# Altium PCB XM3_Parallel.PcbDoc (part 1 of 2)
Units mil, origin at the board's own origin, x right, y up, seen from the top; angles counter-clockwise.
Board outline 8400 x 9001.8 mil, 4 copper layers (TOP, LAYER2, LAYER3, BOTTOM), stack 92 mil thick; 63 components, 9 nets, 170 pads, 4103 vias.
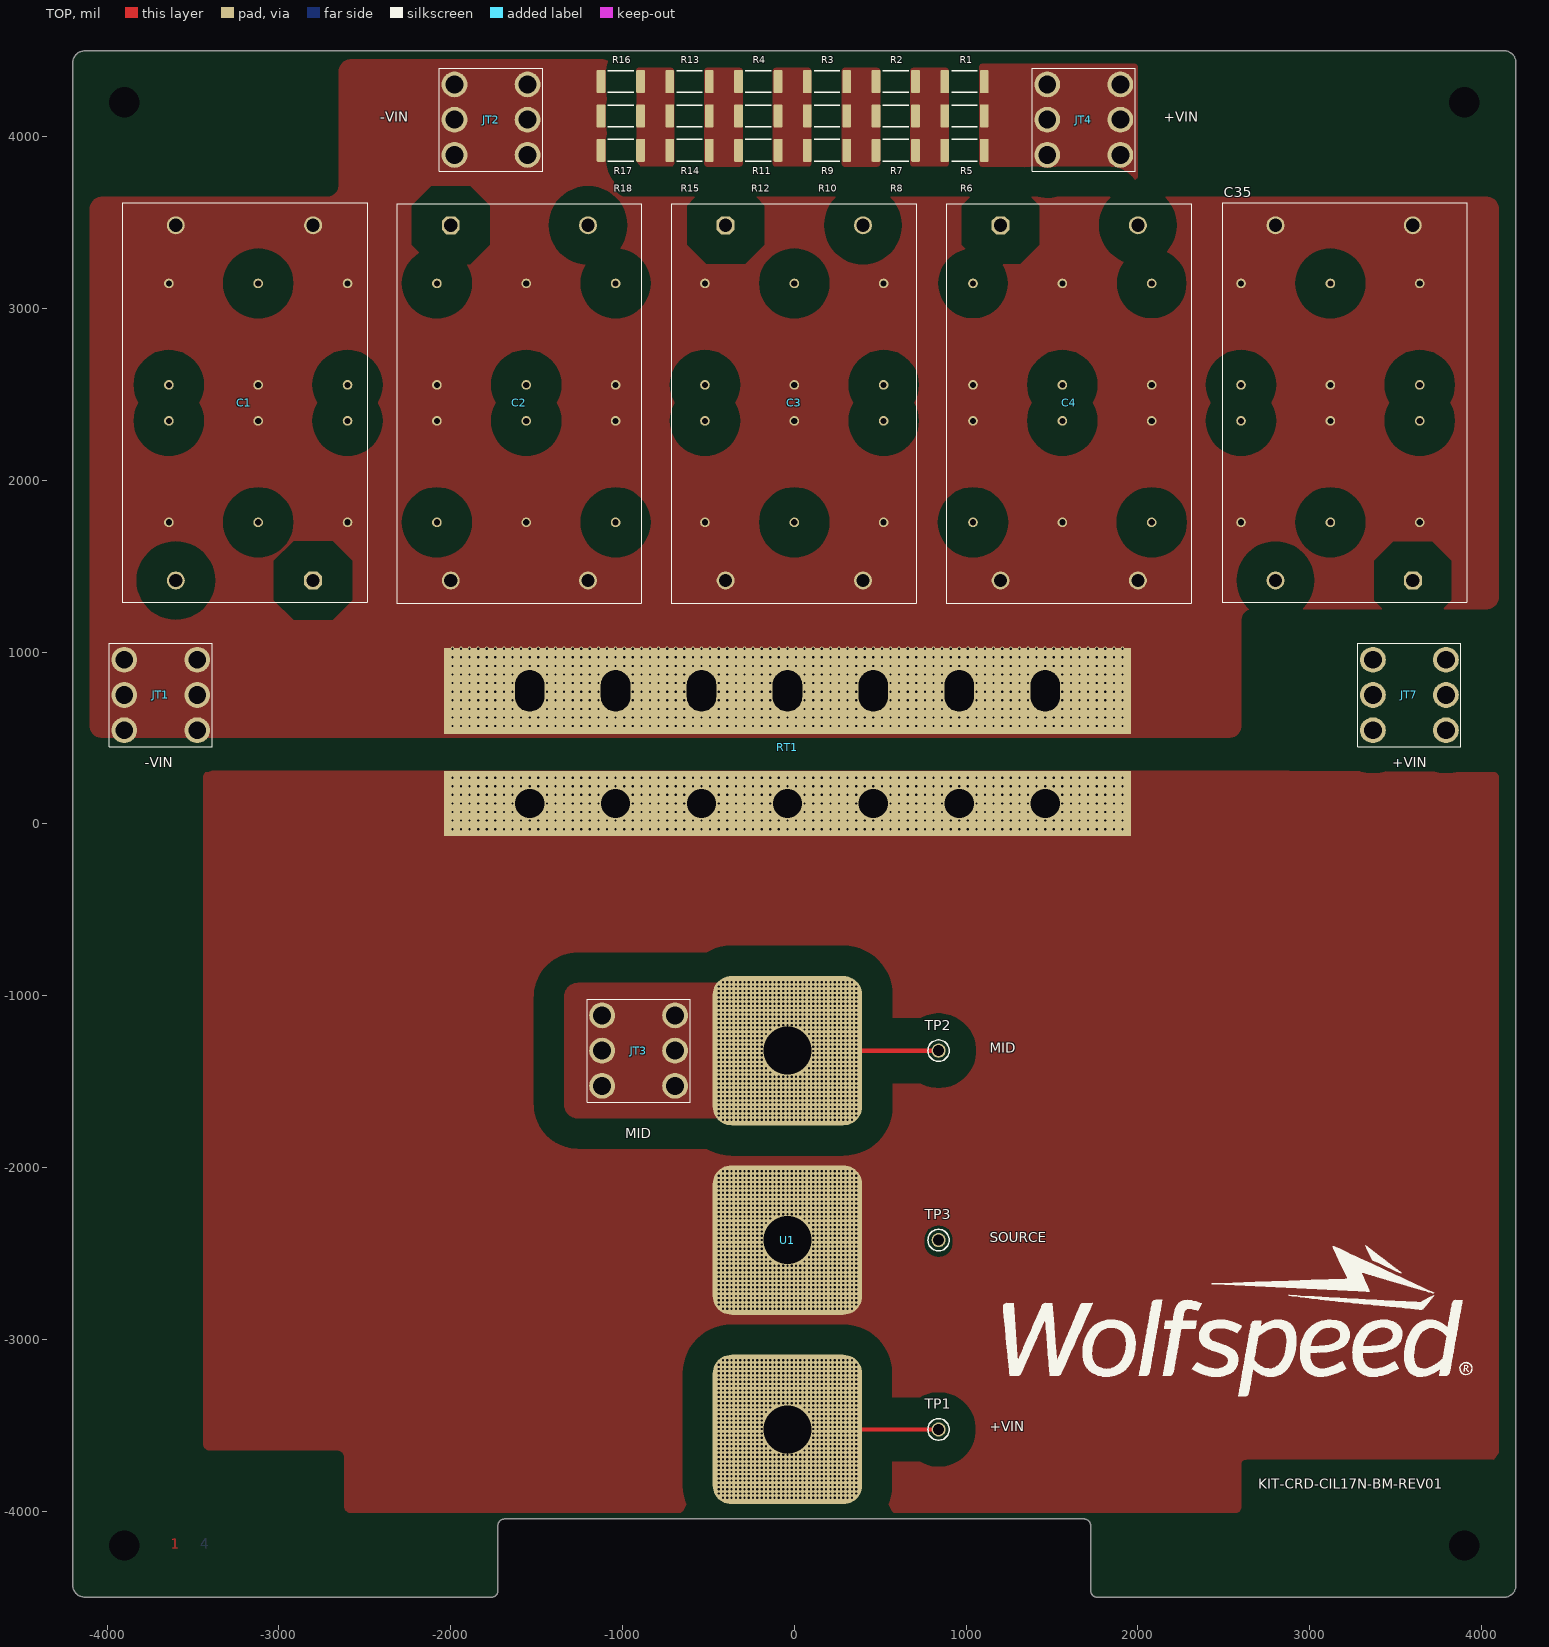
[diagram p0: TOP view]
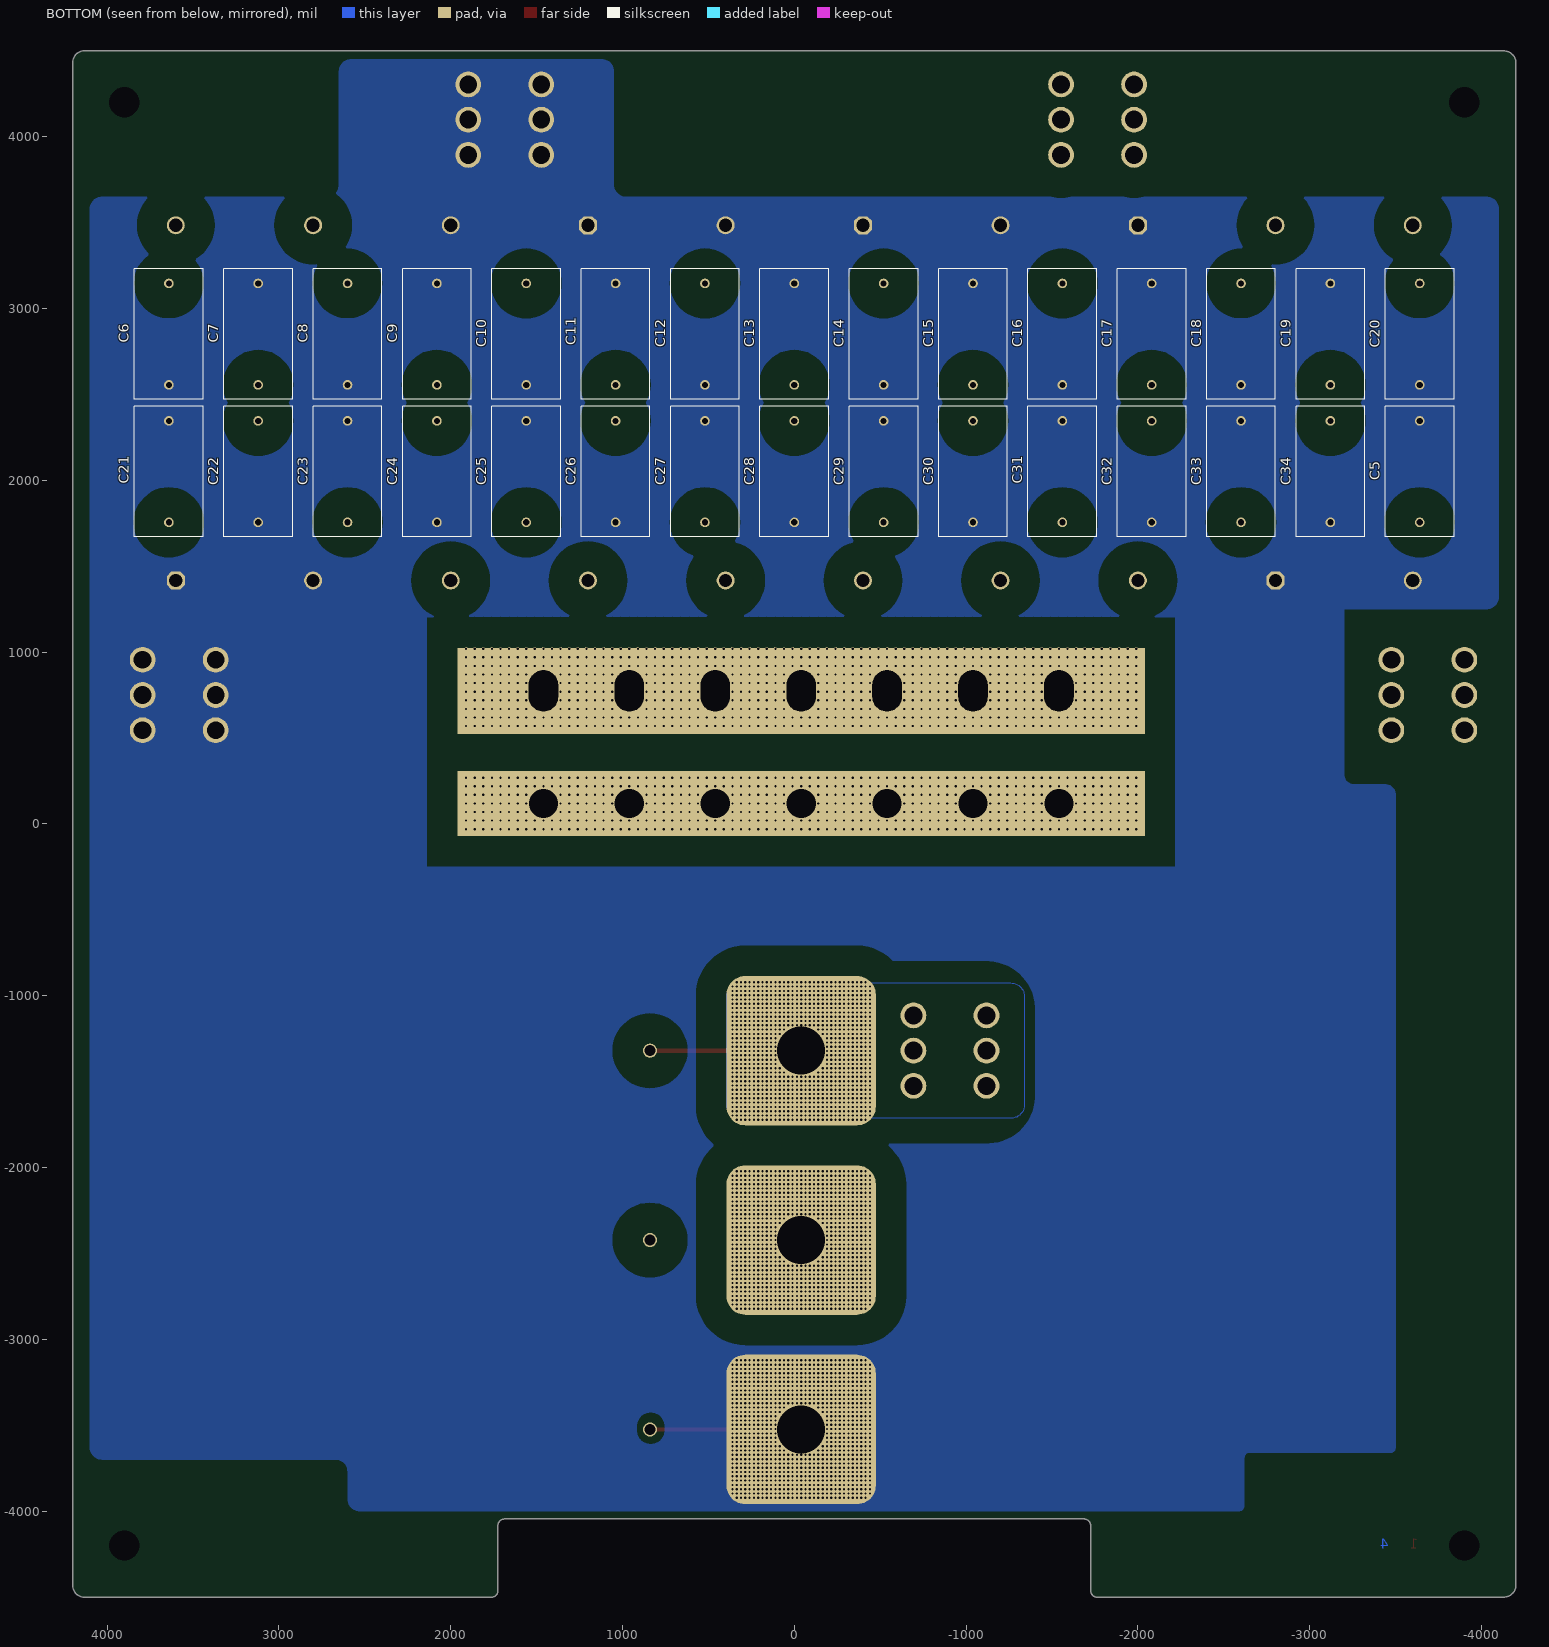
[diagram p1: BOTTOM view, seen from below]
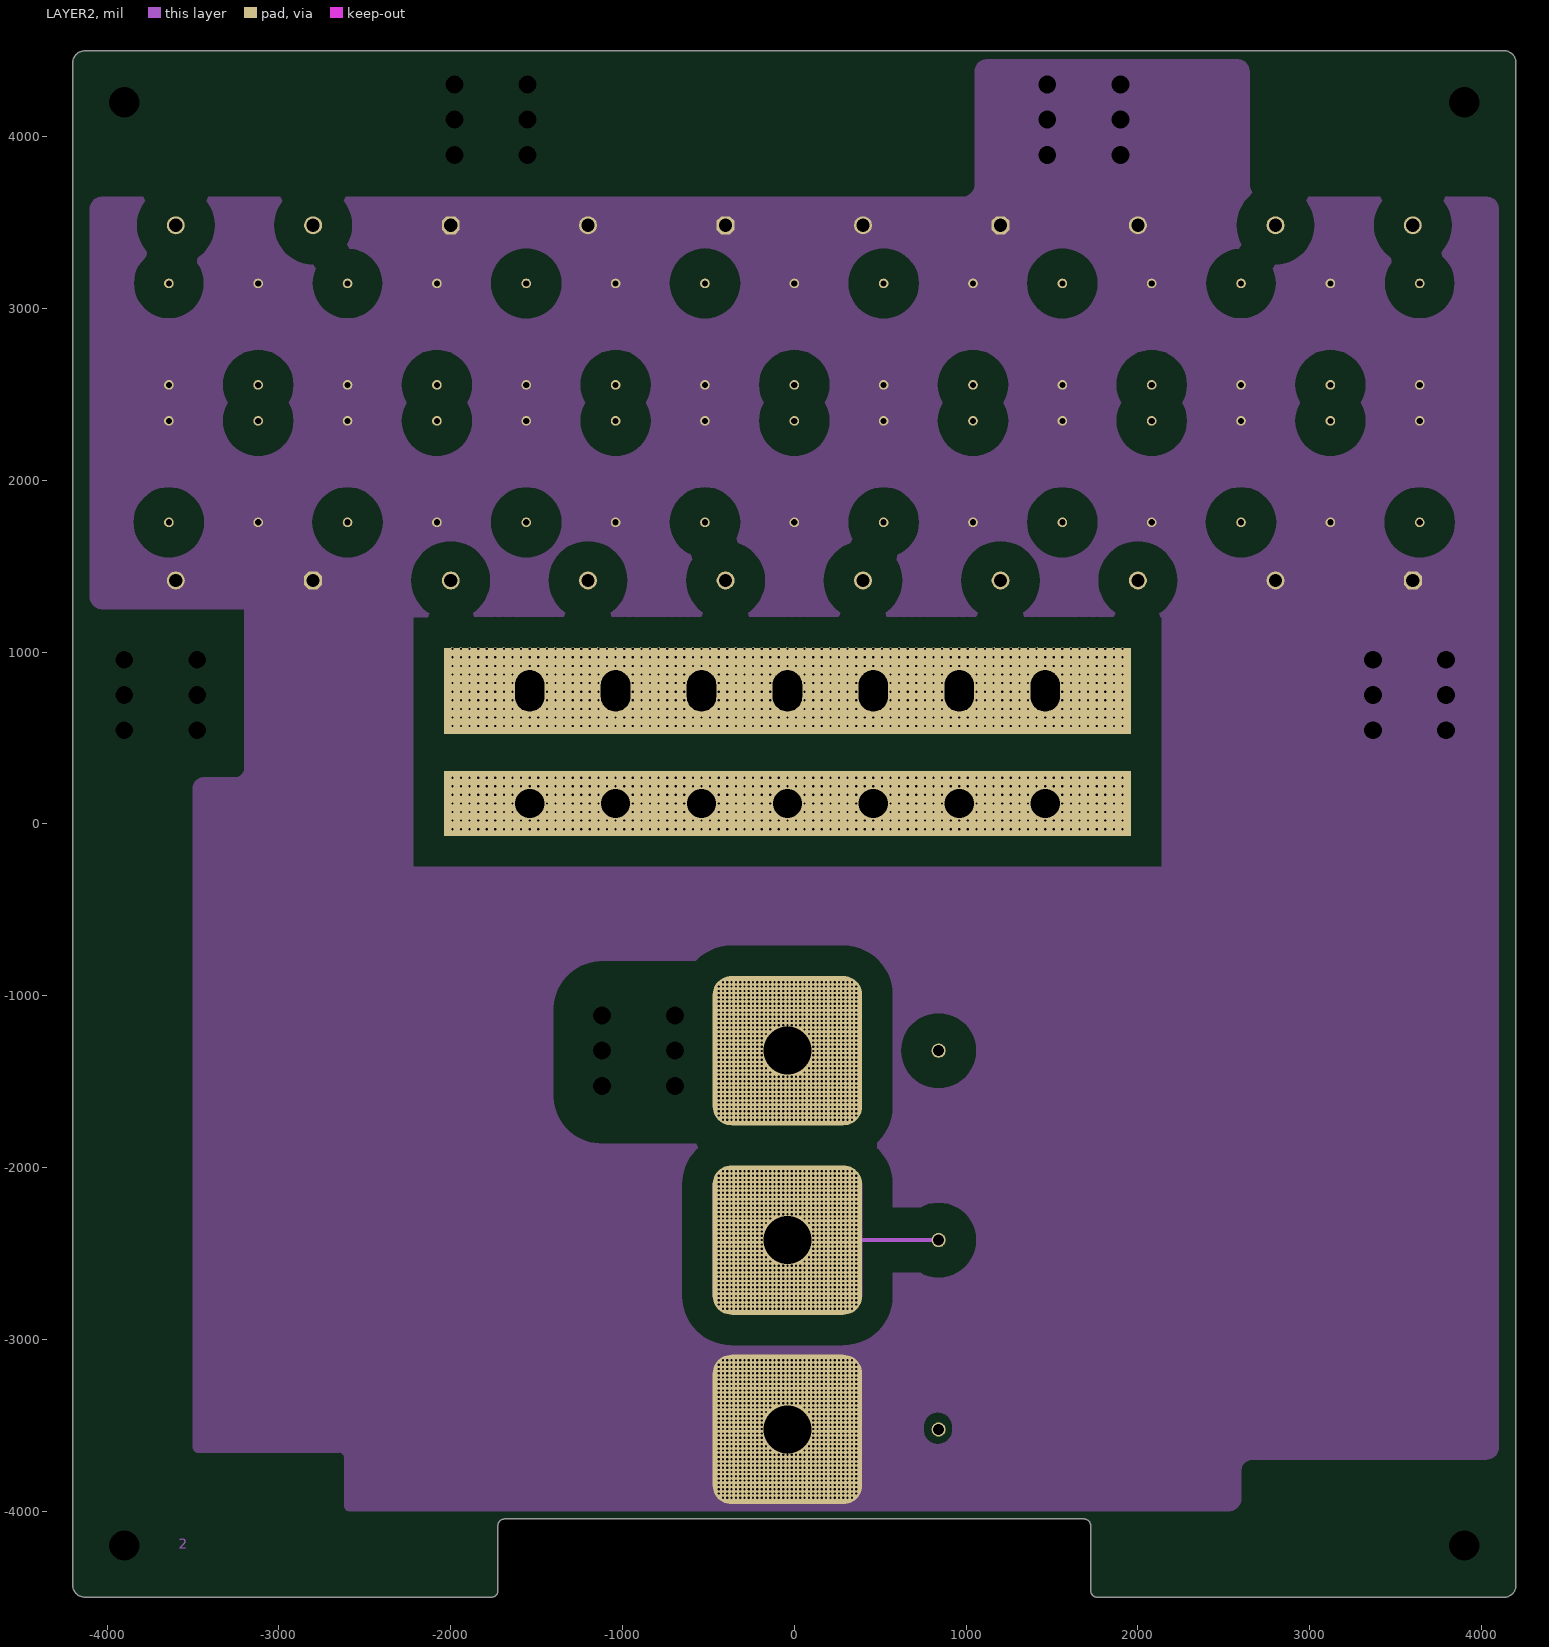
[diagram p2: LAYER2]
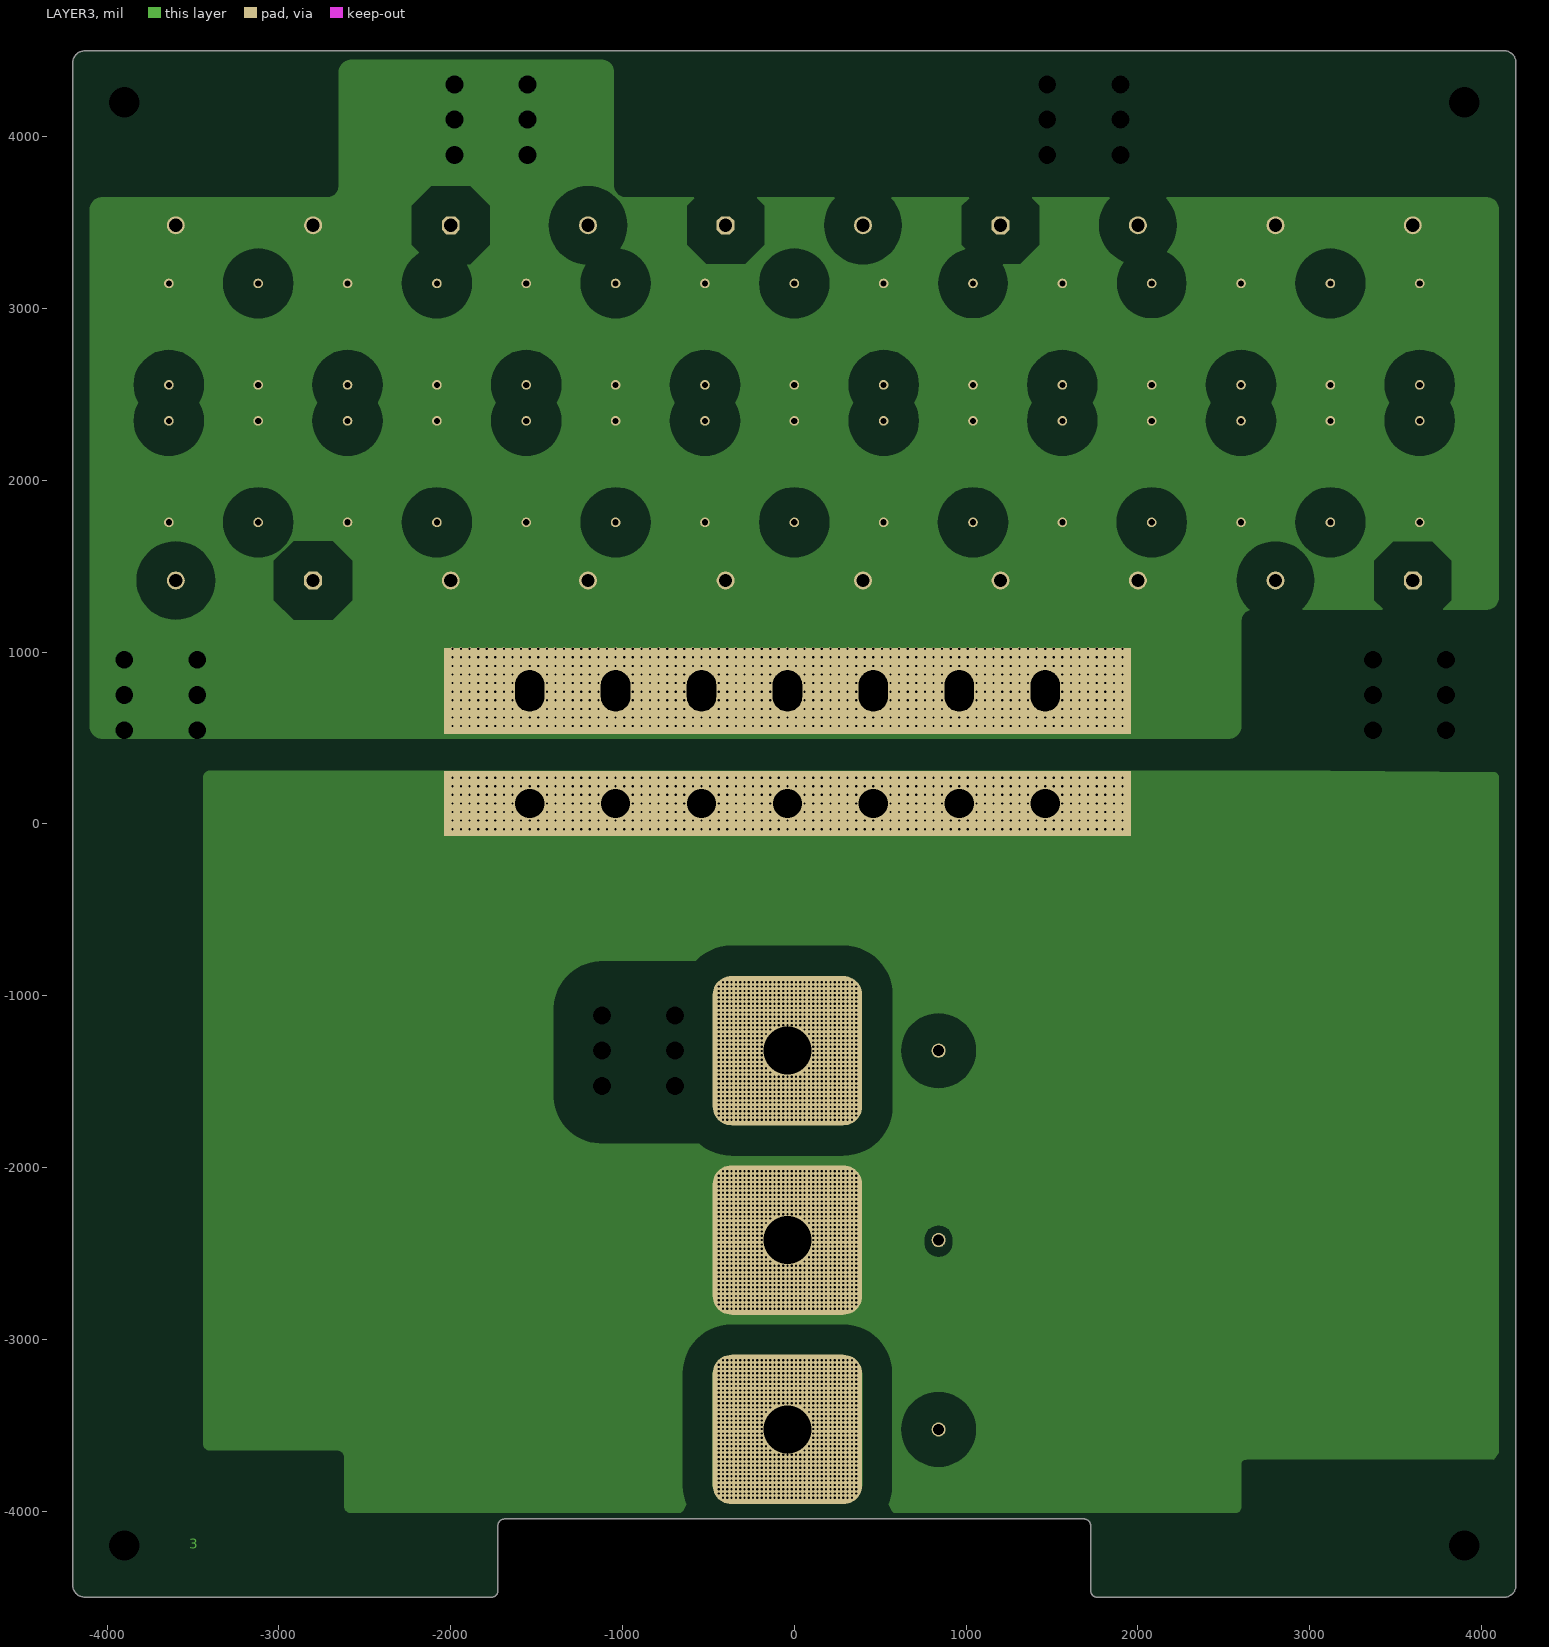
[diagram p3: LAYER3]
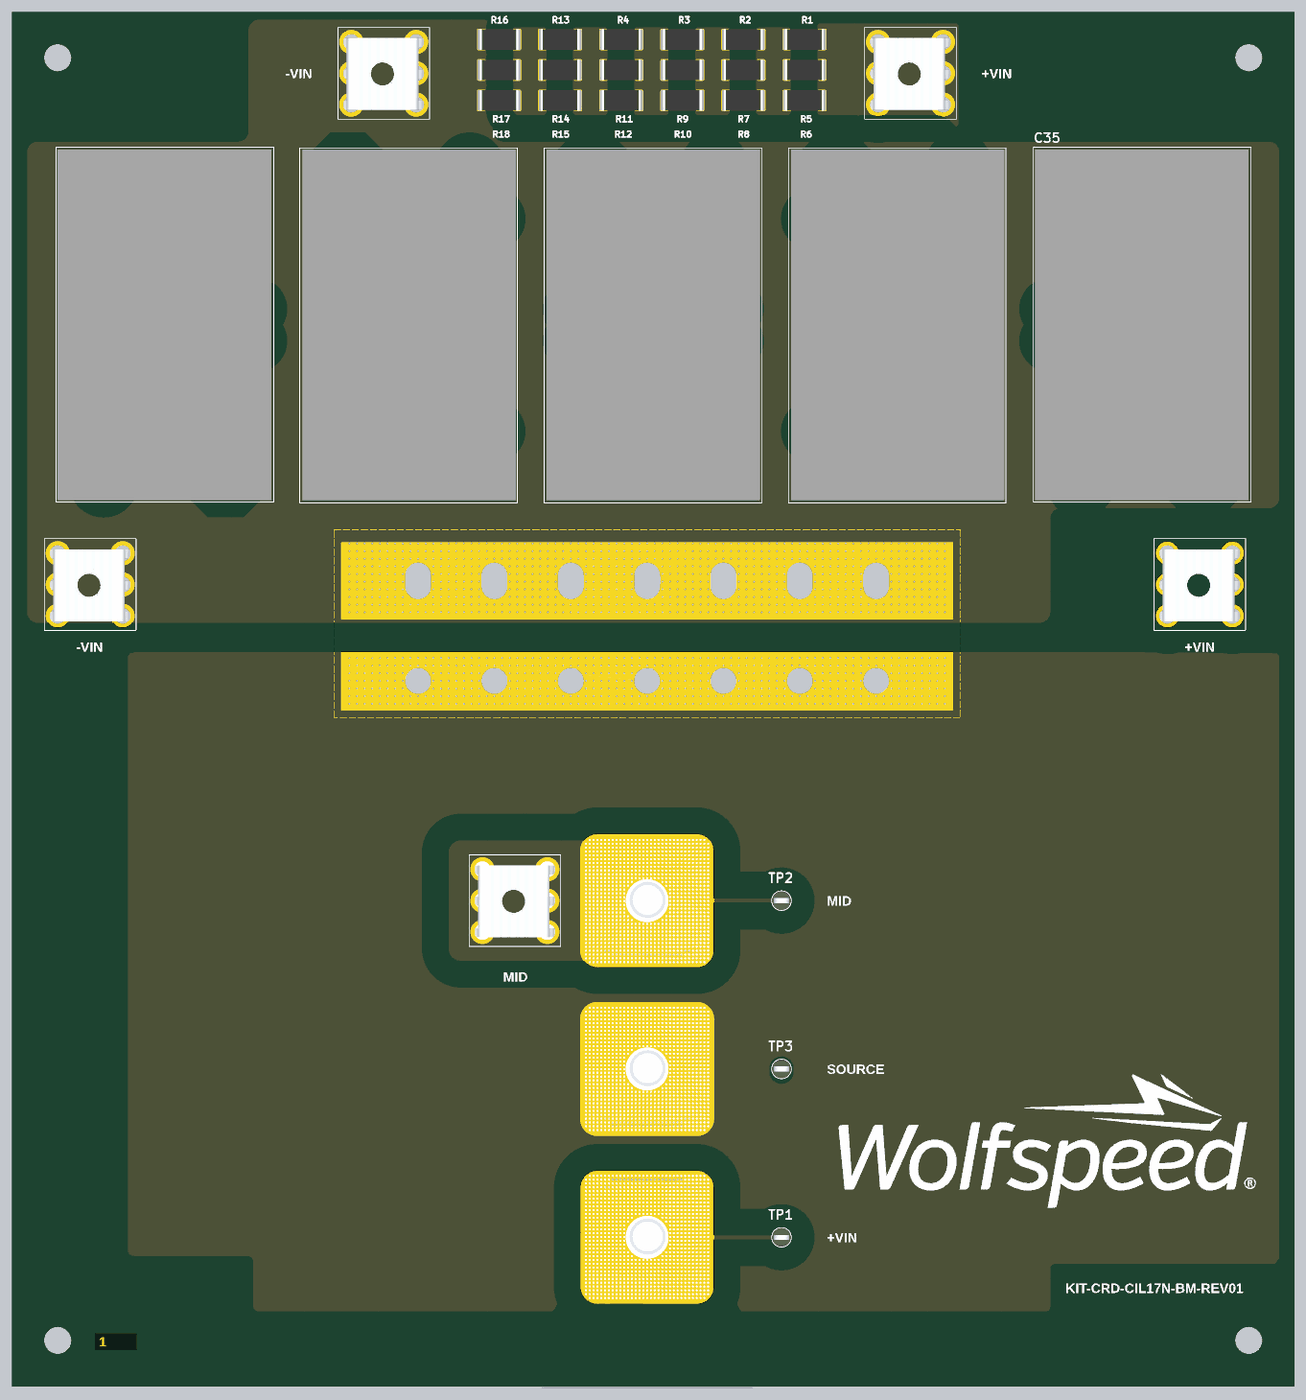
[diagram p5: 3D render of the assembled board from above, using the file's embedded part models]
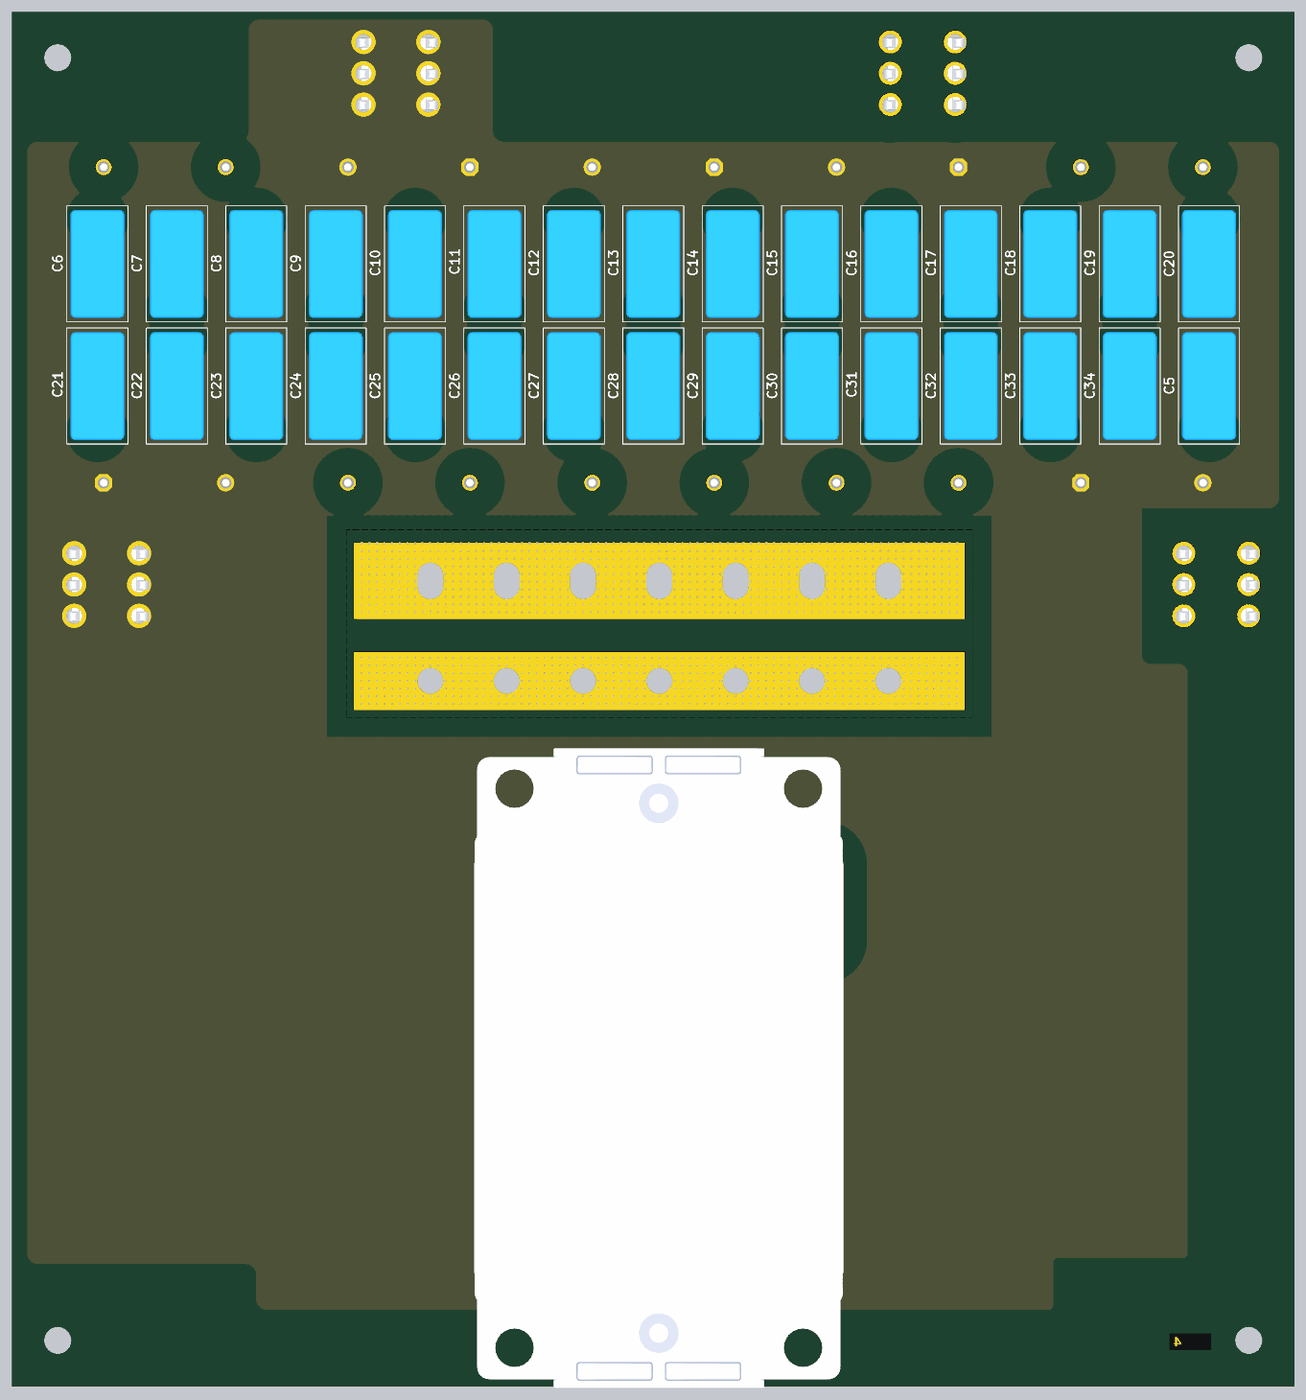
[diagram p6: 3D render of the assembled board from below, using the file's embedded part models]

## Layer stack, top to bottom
TOP: signal copper 2.68
Dielectric 1: core 8, FR-4, Dk 4.5
LAYER2: signal copper 2.68
Dielectric2: core 65.28, FR-4, Dk 4.5
LAYER3: signal copper 2.68
Dielectric3: core 8, FR-4, Dk 4.5
BOTTOM: signal copper 2.68

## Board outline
4130,-4501.8 ccw(c4130,-4431.8) 4200,-4431.8 4200,4430 ccw(c4130,4430) 4130,4500 2952.37,4498.2 -4130,4498.2 ccw(c-4130,4428.2) -4200,4428.2 -4200,-4430 ccw(c-4130,-4430) -4130,-4500 -3286.49,-4501.8 -1764.37,-4501.8 ccw(c-1764.37,-4462.43) -1725,-4462.43 -1725,-4084.79 cw(c-1685.63,-4084.79) -1685.63,-4045.42 1685.63,-4045.42 cw(c1685.63,-4084.79) 1725,-4084.79 1725,-4462.43 ccw(c1764.37,-4462.43) 1764.37,-4501.8

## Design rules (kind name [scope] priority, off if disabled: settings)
Clearance HiPot_Clearance_1 [InNetClass('High_Potential') vs InNetClass('High_Potential')] p1 off: gap=220.47 ignorepadtopadclearanceinfootprint=TRUE
Clearance "Schematic Clearance Constraint_3" [InNet('SOURCE')] p2: gap=175.59 ignorepadtopadclearanceinfootprint=TRUE
Clearance "Schematic Clearance Constraint_2" [InNet('Midpoint')] p3: gap=175.59 ignorepadtopadclearanceinfootprint=TRUE
Clearance "Schematic Clearance Constraint_1" [InNet('+Vin')] p4: gap=175.59 ignorepadtopadclearanceinfootprint=TRUE
Clearance "Schematic Clearance Constraint" [InNet('-Vin')] p5: gap=175.59 ignorepadtopadclearanceinfootprint=TRUE
Clearance [All] p6: gap=10 ignorepadtopadclearanceinfootprint=FALSE except(0: Arc-Hole Track-Hole SMDPad-Hole THPad-Hole Via-Hole Fill-Hole Poly-Hole Region-Hole Text-Hole)
Height [All] p1: minheight=0 maxheight=3000 prefheight=500
HoleSize [All] p1: absolutevalues=TRUE maxlimit=1000 minlimit=1 maxpercent=80.000 minpercent=20.000
PlaneClearance [All] p1: clearance=275.59
PlaneConnect [All] p1: planeconnectstyle=Direct reliefexpansion=20 reliefentries=4 reliefconductorwidth=10 reliefairgap=10
PolygonConnect [All] p1: connectstyle=Direct reliefconductorwidth=10 reliefentries=4 polygonreliefangle="90 Angle" airgapwidth=10
RoomDefinition KIT-CRD-CIL12N-BM_Main [InComponentClass('KIT-CRD-CIL12N-BM_Main')] p1: confinementstyle=ConfineIn formatcopy=TRUE lockcomponents=FALSE outline -4000,-4525 3930,-4525 3930,4415 -4000,4415
RoutingVias [All] p1: holewidth=28 width=50 viastyle="Through Hole" minholewidth=5 minwidth=8 maxholewidth=28 maxwidth=50
SolderMaskExpansion [All] p1: expansion=4 istentingtop=FALSE
Width [All] p1: maxlimit=500 minlimit=5 preferedwidth=25
26 further rules are at their usual default settings.

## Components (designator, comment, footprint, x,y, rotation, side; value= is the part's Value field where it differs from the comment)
C1 "C4AQSBW5220A3NJ" C4AQSBW5220A3NJ -3200,2450 r180 top value=22uF
C2 "C4AQSBW5220A3NJ" C4AQSBW5220A3NJ -1600,2450 r0 top value=22uF
C3 "C4AQSBW5220A3NJ" C4AQSBW5220A3NJ 0,2450 r0 top value=22uF
C4 "C4AQSBW5220A3NJ" C4AQSBW5220A3NJ 1600,2450 r0 top value=22uF
C5 "B32022B3473M000" B32022B3473M000 -3640,2050 r180 bottom
C6 "B32022B3473M000" B32022B3473M000 3640,2850 r0 bottom
C7 "B32022B3473M000" B32022B3473M000 3120,2850 r180 bottom
C8 "B32022B3473M000" B32022B3473M000 2600,2850 r0 bottom
C9 "B32022B3473M000" B32022B3473M000 2080,2850 r180 bottom
C10 "B32022B3473M000" B32022B3473M000 1560,2850 r0 bottom
C11 "B32022B3473M000" B32022B3473M000 1040,2850 r180 bottom
C12 "B32022B3473M000" B32022B3473M000 520,2850 r0 bottom
C13 "B32022B3473M000" B32022B3473M000 0,2850 r180 bottom
C14 "B32022B3473M000" B32022B3473M000 -520,2850 r0 bottom
C15 "B32022B3473M000" B32022B3473M000 -1040,2850 r180 bottom
C16 "B32022B3473M000" B32022B3473M000 -1560,2850 r0 bottom
C17 "B32022B3473M000" B32022B3473M000 -2080,2850 r180 bottom
C18 "B32022B3473M000" B32022B3473M000 -2600,2850 r0 bottom
C19 "B32022B3473M000" B32022B3473M000 -3120,2850 r180 bottom
C20 "B32022B3473M000" B32022B3473M000 -3640,2850 r0 bottom
C21 "B32022B3473M000" B32022B3473M000 3640,2050 r180 bottom
C22 "B32022B3473M000" B32022B3473M000 3120,2050 r0 bottom
C23 "B32022B3473M000" B32022B3473M000 2600,2050 r180 bottom
C24 "B32022B3473M000" B32022B3473M000 2080,2050 r0 bottom
C25 "B32022B3473M000" B32022B3473M000 1560,2050 r180 bottom
C26 "B32022B3473M000" B32022B3473M000 1040,2050 r0 bottom
C27 "B32022B3473M000" B32022B3473M000 520,2050 r180 bottom
C28 "B32022B3473M000" B32022B3473M000 0,2050 r0 bottom
C29 "B32022B3473M000" B32022B3473M000 -520,2050 r180 bottom
C30 "B32022B3473M000" B32022B3473M000 -1040,2050 r0 bottom
C31 "B32022B3473M000" B32022B3473M000 -1560,2050 r180 bottom
C32 "B32022B3473M000" B32022B3473M000 -2080,2050 r0 bottom
C33 "B32022B3473M000" B32022B3473M000 -2600,2050 r180 bottom
C34 "B32022B3473M000" B32022B3473M000 -3120,2050 r0 bottom
C35 "C4AQSBW5220A3NJ" C4AQSBW5220A3NJ 3200,2450 r180 top value=22uF
JT1 "8196" 8196 -3687.21,750 r270 top
JT2 "8196" 8196 -1765,4098.2 r270 top
JT3 "8196" 8196 -906.05,-1319.9 r270 top
JT4 "8196" 8196 1685,4098.2 r270 top
JT7 "8196" 8196 3580,750 r270 top
R1 "2176071-6" RESC6432X06N 990.43,4320 r180 top
R2 "2176071-6" RESC6432X06N 590.43,4320 r0 top
R3 "2176071-6" RESC6432X06N 190.43,4320 r180 top
R4 "2176071-6" RESC6432X06N -209.57,4320 r0 top
R5 "2176071-6" RESC6432X06N 990.43,4120 r180 top
R6 "2176071-6" RESC6432X06N 990.43,3920 r180 top
R7 "2176071-6" RESC6432X06N 590.43,4120 r0 top
R8 "2176071-6" RESC6432X06N 590.43,3920 r0 top
R9 "2176071-6" RESC6432X06N 190.43,4120 r180 top
R10 "2176071-6" RESC6432X06N 190.43,3920 r180 top
R11 "2176071-6" RESC6432X06N -209.57,4120 r0 top
R12 "2176071-6" RESC6432X06N -209.57,3920 r0 top
R13 "2176071-6" RESC6432X06N -609.57,4320 r180 top
R14 "2176071-6" RESC6432X06N -609.57,4120 r180 top
R15 "2176071-6" RESC6432X06N -609.57,3920 r180 top
R16 "2176071-6" RESC6432X06N -1009.57,4320 r0 top
R17 "2176071-6" RESC6432X06N -1009.57,4120 r0 top
R18 "2176071-6" RESC6432X06N -1009.57,3920 r0 top
RT1 "W-2-0025-4FC" tm_cvr_w_14pin_slots -40,493.94 r0 top
TP1 "5011" KSTN-5011_V 840,-3524.76 r0 top
TP2 "5011" KSTN-5011_V 840,-1320.04 r0 top
TP3 "5011" KSTN-5011_V 840,-2422.4 r0 top
U1 "BMx_Module" 62mm_BM_Module -39.95,-2422.4 r0 top

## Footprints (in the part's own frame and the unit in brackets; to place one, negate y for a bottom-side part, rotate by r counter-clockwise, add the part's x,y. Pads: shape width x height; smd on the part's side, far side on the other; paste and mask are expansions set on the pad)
62mm_BM_Module [mil]
  rrect25% 870x870 hole 280: 1(0,1102.36) 2(0,0) 3(0,-1102.36)
  body extent -1205,-2089 1212,2099, height 1168
8196 [mil]
  round 150 / inner round 60 / far side round 150 hole 103.94: 1(-205,-212.5) 2(0,-212.5) 3(205,-212.5) 4(205,212.5) 5(0,212.5) 6(-205,212.5)
  silkscreen extent -300,-300 300,300, body extent -230,-278 240,262, height 454
B32022B3473M000 [mil]
  round 56 hole 36 mask+0: 1(0,-295.28) 2(0,295.28)
  silkscreen extent -200,-380 200,380, body extent -177,-354 177,354, height 689
C4AQSBW5220A3NJ [mm] "C4AQSBW5220A3NJ Unchecked Film; Metallized Polypropylene; DC Link; C4AQ; Automotive Grade; 22 uF; 5%; 1; 50 Film Capacitors 8.13"
  oct 2.65x2.65 hole 1.95: 1(-10.15,26.25)
  round 2.65 hole 1.95: 2(10.15,26.25) 3(-10.15,-26.25) 4(10.15,-26.25)
  silkscreen extent -18.16,-29.59 18.03,29.46, body extent -17.73,-29.15 17.78,29.15, height 50.31
KSTN-5011_V [mm] "Test Point, Dia 3.17mm"
  round 2.1 hole 1.6: 1(0,0)
  silkscreen extent -1.59,-1.58 1.59,1.58, body extent -1.59,-1.59 1.59,1.59, height 8.13
RESC6432X06N [mm] "Chip Resistor, 2-Leads, Body 6.35x3.20mm, IPC Medium Density"
  rrect25% 1.3x3.4 smd: 1(-2.925,0) 2(2.925,0)
  silkscreen extent -1.9,-1.6 1.9,1.6, body extent -3.22,-1.7 3.22,1.7, height 0.65
tm_cvr_w_14pin_slots [mil]
  round 300 / inner round 60 / far side round 300 hole 170: 1(-1500,-375) 2(-1000,-375) 3(-500,-375) 5(500,-375) 6(1000,-375) 7(1500,-375)
  rect 4000x380 hole 170: 4(0,-375)
  oval 300x370 / inner round 60 / far side oval 300x370 hole 170 slot 240 at 90 deg: 8(1500,280) 9(1000,280) 10(500,280) 12(-500,280) 13(-1000,280) 14(-1500,280)
  rect 4000x500 hole 170 slot 240 at 90 deg: 11(0,280)

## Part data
C1 C2 C3 C4 C35: "C4AQSBW5220A3NJ Unchecked Film; Metallized Polypropylene; DC Link; C4AQ; Automotive Grade; 22 uF; 5%; 1; 50 Film Capacitors 8.13", Manufacturer=Kemet, Tolerence=5%, Voltage Rating=1500VDC
C5 C6 C7 C8 C9 C10 C11 C12 C13 C14 C15 C16 C17 C18 C19 C20 C21 C22 C23 C24 C25 C26 C27 C28 C29 C30 C31 C32 C33 C34: "Cap Film 0.047uF 300VAC PP 20% 18 X 9 X 17.5mm RDL 15mm Bulk", Capacitance=47nF, Dielectric=PP, Dielectric Material=Polypropylene, Insulation Resistance=100R, Manufacturer="TDK EPCOS", Max Operating Temperature=110°C, Min Operating Temperature=-40°C, Supplier Part Number 1=495-4769-ND, Tolerance=20%, Voltage=1.5kV
JT1 JT2 JT3 JT4 JT7: library part "Conn Plug 6", "TERMINAL SCREW PC HEAVY DUTY", Manufacturer="Keystone Electronics"
R1 R2 R3 R4 R5 R6 R7 R8 R9 R10 R11 R12 R13 R14 R15 R16 R17 R18: "Res Thick Film 2512 220K Ohm 1% 2W ±100ppm/°C Molded SMD T/R", Case Code (Imperial)=2512, Case Code (Metric)=6432, Manufacturer="TE Connectivity", Max Operating Temperature=155°C, Max Power Dissipation=2W, Min Operating Temperature=-55°C, Package Quantity=4000, Resistance=220kR, Resistor Type="Thick Film", Supplier Part Number 1=01AH0733, Temperature Coefficient=100ppm/°C, Tolerance=1%
TP1 TP2 TP3: "Test Point, Black, Through Hole, RoHS, Bulk", Colour=Black, Manufacturer=Keystone, Package Quantity=100

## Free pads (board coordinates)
  round 104.33 hole 177.17 unplated: 0(-3900,-4200) 1(3900,-4200) 2(3900,4200) 3(-3900,4200)

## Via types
v1: diameter 24/20/20/20 (per signal layer), hole 13, TOP to BOTTOM, tented both sides, 4103 vias

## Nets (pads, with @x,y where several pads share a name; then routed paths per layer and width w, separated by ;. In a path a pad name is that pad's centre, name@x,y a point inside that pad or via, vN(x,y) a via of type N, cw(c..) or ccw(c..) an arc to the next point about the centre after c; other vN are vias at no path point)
+VIN: C1.1 C1.2 C2.1 C2.2 C3.1 C3.2 C4.1 C4.2 C5.2 C6.2 C7.2 C8.2 C9.2 C10.2 C11.2 C12.2 C13.2 C14.2 C15.2 C16.2 C17.2 C18.2 C19.2 C20.2 C21.2 C22.2 C23.2 C24.2 C25.2 C26.2 C27.2 C28.2 C29.2 C30.2 C31.2 C32.2 C33.2 C34.2 C35.1 C35.2 JT4.1 JT4.2 JT4.3 JT4.4 JT4.5 JT4.6 JT7.1 JT7.2 JT7.3 JT7.4 JT7.5 JT7.6 R1.1 R5.1 R6.1 TP1.1 U1.3 | length 880
  TOP w25: U1.3@-39.95,-3524.76 310.05,-3524.76 TP1.1@840,-3524.76
  other v1: -414.95,-3922.4 -389.95,-3922.4 -364.95,-3922.4 -339.95,-3922.4 -314.95,-3922.4 -289.95,-3922.4 -264.95,-3922.4 -239.95,-3922.4 -214.95,-3922.4 -189.95,-3922.4 -164.95,-3922.4 -139.95,-3922.4 -114.95,-3922.4 -89.95,-3922.4 -64.95,-3922.4 -39.95,-3922.4 -14.95,-3922.4 10.05,-3922.4 35.05,-3922.4 60.05,-3922.4 85.05,-3922.4 110.05,-3922.4 135.05,-3922.4 160.05,-3922.4 185.05,-3922.4 210.05,-3922.4 235.05,-3922.4 260.05,-3922.4 285.05,-3922.4 310.05,-3922.4 335.05,-3922.4 -439.95,-3897.4 -414.95,-3897.4 -389.95,-3897.4 -364.95,-3897.4 -339.95,-3897.4 -314.95,-3897.4 -289.95,-3897.4 -264.95,-3897.4 -239.95,-3897.4 -214.95,-3897.4 -189.95,-3897.4 -164.95,-3897.4 -139.95,-3897.4 -114.95,-3897.4 -89.95,-3897.4 -64.95,-3897.4 -39.95,-3897.4 -14.95,-3897.4 10.05,-3897.4 35.05,-3897.4 60.05,-3897.4 85.05,-3897.4 110.05,-3897.4 135.05,-3897.4 160.05,-3897.4 185.05,-3897.4 210.05,-3897.4 235.05,-3897.4 260.05,-3897.4 285.05,-3897.4 310.05,-3897.4 335.05,-3897.4 360.05,-3897.4 -439.95,-3872.4 -414.95,-3872.4 -389.95,-3872.4 -364.95,-3872.4 -339.95,-3872.4 -314.95,-3872.4 -289.95,-3872.4 -264.95,-3872.4 -239.95,-3872.4 -214.95,-3872.4 -189.95,-3872.4 -164.95,-3872.4 -139.95,-3872.4 -114.95,-3872.4 -89.95,-3872.4 -64.95,-3872.4 -39.95,-3872.4 -14.95,-3872.4 10.05,-3872.4 35.05,-3872.4 60.05,-3872.4 85.05,-3872.4 110.05,-3872.4 135.05,-3872.4 160.05,-3872.4 185.05,-3872.4 210.05,-3872.4 235.05,-3872.4 260.05,-3872.4 285.05,-3872.4 310.05,-3872.4 335.05,-3872.4 360.05,-3872.4 -439.95,-3847.4 -414.95,-3847.4 -389.95,-3847.4 -364.95,-3847.4 -339.95,-3847.4 -314.95,-3847.4 -289.95,-3847.4 -264.95,-3847.4 -239.95,-3847.4 -214.95,-3847.4 -189.95,-3847.4 -164.95,-3847.4 -139.95,-3847.4 -114.95,-3847.4 -89.95,-3847.4 -64.95,-3847.4 -39.95,-3847.4 -14.95,-3847.4 10.05,-3847.4 35.05,-3847.4 60.05,-3847.4 85.05,-3847.4 110.05,-3847.4 135.05,-3847.4 160.05,-3847.4 185.05,-3847.4 210.05,-3847.4 235.05,-3847.4 260.05,-3847.4 285.05,-3847.4 310.05,-3847.4 335.05,-3847.4 360.05,-3847.4 -439.95,-3822.4 -414.95,-3822.4 -389.95,-3822.4 -364.95,-3822.4 -339.95,-3822.4 -314.95,-3822.4 -289.95,-3822.4 -264.95,-3822.4 -239.95,-3822.4 -214.95,-3822.4 -189.95,-3822.4 -164.95,-3822.4 -139.95,-3822.4 -114.95,-3822.4 -89.95,-3822.4 -64.95,-3822.4 -39.95,-3822.4 -14.95,-3822.4 10.05,-3822.4 35.05,-3822.4 60.05,-3822.4 85.05,-3822.4 110.05,-3822.4 135.05,-3822.4 160.05,-3822.4 185.05,-3822.4 210.05,-3822.4 235.05,-3822.4 260.05,-3822.4 285.05,-3822.4 310.05,-3822.4 335.05,-3822.4 360.05,-3822.4 -439.95,-3797.4 -414.95,-3797.4 -389.95,-3797.4 -364.95,-3797.4 -339.95,-3797.4 -314.95,-3797.4 -289.95,-3797.4 -264.95,-3797.4 -239.95,-3797.4 -214.95,-3797.4 -189.95,-3797.4 -164.95,-3797.4 -139.95,-3797.4 -114.95,-3797.4 -89.95,-3797.4 -64.95,-3797.4 -39.95,-3797.4 -14.95,-3797.4 10.05,-3797.4 35.05,-3797.4 60.05,-3797.4 85.05,-3797.4 110.05,-3797.4 135.05,-3797.4 160.05,-3797.4 185.05,-3797.4 210.05,-3797.4 235.05,-3797.4 260.05,-3797.4 285.05,-3797.4 310.05,-3797.4 335.05,-3797.4 360.05,-3797.4 -439.95,-3772.4 -414.95,-3772.4 -389.95,-3772.4 -364.95,-3772.4 -339.95,-3772.4 -314.95,-3772.4 -289.95,-3772.4 -264.95,-3772.4 -239.95,-3772.4 -214.95,-3772.4 -189.95,-3772.4 -164.95,-3772.4 -139.95,-3772.4 -114.95,-3772.4 -89.95,-3772.4 -64.95,-3772.4 -39.95,-3772.4 -14.95,-3772.4 10.05,-3772.4 35.05,-3772.4 60.05,-3772.4 85.05,-3772.4 110.05,-3772.4 135.05,-3772.4 160.05,-3772.4 185.05,-3772.4 210.05,-3772.4 235.05,-3772.4 260.05,-3772.4 285.05,-3772.4 310.05,-3772.4 335.05,-3772.4 360.05,-3772.4 -439.95,-3747.4 -414.95,-3747.4 -389.95,-3747.4 -364.95,-3747.4 -339.95,-3747.4 -314.95,-3747.4 -289.95,-3747.4 -264.95,-3747.4 -239.95,-3747.4 -214.95,-3747.4 -189.95,-3747.4 -164.95,-3747.4 -139.95,-3747.4 -114.95,-3747.4 -89.95,-3747.4 -64.95,-3747.4 -39.95,-3747.4 -14.95,-3747.4 10.05,-3747.4 35.05,-3747.4 60.05,-3747.4 85.05,-3747.4 110.05,-3747.4 135.05,-3747.4 160.05,-3747.4 185.05,-3747.4 210.05,-3747.4 235.05,-3747.4 260.05,-3747.4 285.05,-3747.4 310.05,-3747.4 335.05,-3747.4 360.05,-3747.4 -439.95,-3722.4 -414.95,-3722.4 -389.95,-3722.4 -364.95,-3722.4 -339.95,-3722.4 -314.95,-3722.4 -289.95,-3722.4 -264.95,-3722.4 -239.95,-3722.4 -214.95,-3722.4 -189.95,-3722.4 -164.95,-3722.4 -139.95,-3722.4 -114.95,-3722.4 -89.95,-3722.4 -64.95,-3722.4 -39.95,-3722.4 -14.95,-3722.4 10.05,-3722.4 35.05,-3722.4 60.05,-3722.4 85.05,-3722.4 110.05,-3722.4 135.05,-3722.4 160.05,-3722.4 185.05,-3722.4 210.05,-3722.4 235.05,-3722.4 260.05,-3722.4 285.05,-3722.4 310.05,-3722.4 335.05,-3722.4 360.05,-3722.4 -439.95,-3697.4 -414.95,-3697.4 -389.95,-3697.4 -364.95,-3697.4 -339.95,-3697.4 -314.95,-3697.4 -289.95,-3697.4 -264.95,-3697.4 -239.95,-3697.4 -214.95,-3697.4 -189.95,-3697.4 -164.95,-3697.4 -139.95,-3697.4 -114.95,-3697.4 -89.95,-3697.4 -64.95,-3697.4 -39.95,-3697.4 -14.95,-3697.4 10.05,-3697.4 35.05,-3697.4 60.05,-3697.4 85.05,-3697.4 110.05,-3697.4 135.05,-3697.4 160.05,-3697.4 185.05,-3697.4 210.05,-3697.4 235.05,-3697.4 260.05,-3697.4 285.05,-3697.4 310.05,-3697.4 335.05,-3697.4 360.05,-3697.4 -439.95,-3672.4 -414.95,-3672.4 -389.95,-3672.4 -364.95,-3672.4 -339.95,-3672.4 -314.95,-3672.4 -289.95,-3672.4 -264.95,-3672.4 -239.95,-3672.4 -214.95,-3672.4 -189.95,-3672.4 -164.95,-3672.4 -139.95,-3672.4 -114.95,-3672.4 -89.95,-3672.4 -64.95,-3672.4 -39.95,-3672.4 -14.95,-3672.4 10.05,-3672.4 35.05,-3672.4 60.05,-3672.4 85.05,-3672.4 110.05,-3672.4 135.05,-3672.4 160.05,-3672.4 185.05,-3672.4 210.05,-3672.4 235.05,-3672.4 260.05,-3672.4 285.05,-3672.4 310.05,-3672.4 335.05,-3672.4 360.05,-3672.4 -439.95,-3647.4 -414.95,-3647.4 -389.95,-3647.4 -364.95,-3647.4 -339.95,-3647.4 -314.95,-3647.4 -289.95,-3647.4 -264.95,-3647.4 -239.95,-3647.4 -214.95,-3647.4 -189.95,-3647.4 -164.95,-3647.4 -139.95,-3647.4 60.05,-3647.4 85.05,-3647.4 110.05,-3647.4 135.05,-3647.4 160.05,-3647.4 185.05,-3647.4 210.05,-3647.4 235.05,-3647.4 260.05,-3647.4 285.05,-3647.4 310.05,-3647.4 335.05,-3647.4 360.05,-3647.4 -439.95,-3622.4 -414.95,-3622.4 -389.95,-3622.4 -364.95,-3622.4 -339.95,-3622.4 -314.95,-3622.4 -289.95,-3622.4 -264.95,-3622.4 -239.95,-3622.4 -214.95,-3622.4 -189.95,-3622.4 -164.95,-3622.4 85.05,-3622.4 110.05,-3622.4 135.05,-3622.4 160.05,-3622.4 185.05,-3622.4 210.05,-3622.4 235.05,-3622.4 260.05,-3622.4 285.05,-3622.4 310.05,-3622.4 335.05,-3622.4 360.05,-3622.4 -439.95,-3597.4 -414.95,-3597.4 -389.95,-3597.4 -364.95,-3597.4 -339.95,-3597.4 -314.95,-3597.4 -289.95,-3597.4 -264.95,-3597.4 -239.95,-3597.4 -214.95,-3597.4 -189.95,-3597.4 110.05,-3597.4 135.05,-3597.4 160.05,-3597.4 185.05,-3597.4 210.05,-3597.4 235.05,-3597.4 260.05,-3597.4 285.05,-3597.4 310.05,-3597.4 335.05,-3597.4 360.05,-3597.4 -439.95,-3572.4 -414.95,-3572.4 -389.95,-3572.4 -364.95,-3572.4 -339.95,-3572.4 -314.95,-3572.4 -289.95,-3572.4 -264.95,-3572.4 -239.95,-3572.4 -214.95,-3572.4 -189.95,-3572.4 110.05,-3572.4 135.05,-3572.4 160.05,-3572.4 185.05,-3572.4 210.05,-3572.4 235.05,-3572.4 260.05,-3572.4 285.05,-3572.4 310.05,-3572.4 335.05,-3572.4 360.05,-3572.4 -439.95,-3547.4 -414.95,-3547.4 -389.95,-3547.4 -364.95,-3547.4 -339.95,-3547.4 -314.95,-3547.4 -289.95,-3547.4 -264.95,-3547.4 -239.95,-3547.4 -214.95,-3547.4 -189.95,-3547.4 110.05,-3547.4 135.05,-3547.4 160.05,-3547.4 185.05,-3547.4 210.05,-3547.4 235.05,-3547.4 260.05,-3547.4 285.05,-3547.4 310.05,-3547.4 335.05,-3547.4 360.05,-3547.4 -439.95,-3522.4 -414.95,-3522.4 -389.95,-3522.4 -364.95,-3522.4 -339.95,-3522.4 -314.95,-3522.4 -289.95,-3522.4 -264.95,-3522.4 -239.95,-3522.4 -214.95,-3522.4 -189.95,-3522.4 110.05,-3522.4 135.05,-3522.4 160.05,-3522.4 185.05,-3522.4 210.05,-3522.4 235.05,-3522.4 260.05,-3522.4 285.05,-3522.4 310.05,-3522.4 335.05,-3522.4 360.05,-3522.4 -439.95,-3497.4 -414.95,-3497.4 -389.95,-3497.4 -364.95,-3497.4 -339.95,-3497.4 -314.95,-3497.4 -289.95,-3497.4 -264.95,-3497.4 -239.95,-3497.4 -214.95,-3497.4 -189.95,-3497.4 110.05,-3497.4 135.05,-3497.4 160.05,-3497.4 185.05,-3497.4 210.05,-3497.4 235.05,-3497.4 260.05,-3497.4 285.05,-3497.4 310.05,-3497.4 335.05,-3497.4 360.05,-3497.4 -439.95,-3472.4 -414.95,-3472.4 -389.95,-3472.4 -364.95,-3472.4 -339.95,-3472.4 -314.95,-3472.4 -289.95,-3472.4 -264.95,-3472.4 -239.95,-3472.4 -214.95,-3472.4 -189.95,-3472.4 110.05,-3472.4 135.05,-3472.4 160.05,-3472.4 185.05,-3472.4 210.05,-3472.4 235.05,-3472.4 260.05,-3472.4 285.05,-3472.4 310.05,-3472.4 335.05,-3472.4 360.05,-3472.4 -439.95,-3447.4 -414.95,-3447.4 -389.95,-3447.4 -364.95,-3447.4 -339.95,-3447.4 -314.95,-3447.4 -289.95,-3447.4 -264.95,-3447.4 -239.95,-3447.4 -214.95,-3447.4 -189.95,-3447.4 110.05,-3447.4 135.05,-3447.4 160.05,-3447.4 185.05,-3447.4 210.05,-3447.4 235.05,-3447.4 260.05,-3447.4 285.05,-3447.4 310.05,-3447.4 335.05,-3447.4 360.05,-3447.4 -439.95,-3422.4 -414.95,-3422.4 -389.95,-3422.4 -364.95,-3422.4 -339.95,-3422.4 -314.95,-3422.4 -289.95,-3422.4 -264.95,-3422.4 -239.95,-3422.4 -214.95,-3422.4 -189.95,-3422.4 -164.95,-3422.4 85.05,-3422.4 110.05,-3422.4 135.05,-3422.4 160.05,-3422.4 185.05,-3422.4 210.05,-3422.4 235.05,-3422.4 260.05,-3422.4 285.05,-3422.4 310.05,-3422.4 335.05,-3422.4 360.05,-3422.4 -439.95,-3397.4 -414.95,-3397.4 -389.95,-3397.4 -364.95,-3397.4 -339.95,-3397.4 -314.95,-3397.4 -289.95,-3397.4 -264.95,-3397.4 -239.95,-3397.4 -214.95,-3397.4 -189.95,-3397.4 -164.95,-3397.4 -139.95,-3397.4 60.05,-3397.4 85.05,-3397.4 110.05,-3397.4 135.05,-3397.4 160.05,-3397.4 185.05,-3397.4 210.05,-3397.4 235.05,-3397.4 260.05,-3397.4 285.05,-3397.4 310.05,-3397.4 335.05,-3397.4 360.05,-3397.4 -439.95,-3372.4 -414.95,-3372.4 -389.95,-3372.4 -364.95,-3372.4 -339.95,-3372.4 -314.95,-3372.4 -289.95,-3372.4 -264.95,-3372.4 -239.95,-3372.4 -214.95,-3372.4 -189.95,-3372.4 -164.95,-3372.4 -139.95,-3372.4 -114.95,-3372.4 -89.95,-3372.4 -64.95,-3372.4 -39.95,-3372.4 -14.95,-3372.4 10.05,-3372.4 35.05,-3372.4 60.05,-3372.4 85.05,-3372.4 110.05,-3372.4 135.05,-3372.4 160.05,-3372.4 185.05,-3372.4 210.05,-3372.4 235.05,-3372.4 260.05,-3372.4 285.05,-3372.4 310.05,-3372.4 335.05,-3372.4 360.05,-3372.4 -439.95,-3347.4 -414.95,-3347.4 -389.95,-3347.4 -364.95,-3347.4 -339.95,-3347.4 -314.95,-3347.4 -289.95,-3347.4 -264.95,-3347.4 -239.95,-3347.4 -214.95,-3347.4 -189.95,-3347.4 -164.95,-3347.4 -139.95,-3347.4 -114.95,-3347.4 -89.95,-3347.4 -64.95,-3347.4 -39.95,-3347.4 -14.95,-3347.4 10.05,-3347.4 35.05,-3347.4 60.05,-3347.4 85.05,-3347.4 110.05,-3347.4 135.05,-3347.4 160.05,-3347.4 185.05,-3347.4 210.05,-3347.4 235.05,-3347.4 260.05,-3347.4 285.05,-3347.4 310.05,-3347.4 335.05,-3347.4 360.05,-3347.4 -439.95,-3322.4 -414.95,-3322.4 -389.95,-3322.4 -364.95,-3322.4 -339.95,-3322.4 -314.95,-3322.4 -289.95,-3322.4 -264.95,-3322.4 -239.95,-3322.4 -214.95,-3322.4 -189.95,-3322.4 -164.95,-3322.4 -139.95,-3322.4 -114.95,-3322.4 -89.95,-3322.4 -64.95,-3322.4 -39.95,-3322.4 -14.95,-3322.4 10.05,-3322.4 35.05,-3322.4 60.05,-3322.4 85.05,-3322.4 110.05,-3322.4 135.05,-3322.4 160.05,-3322.4 185.05,-3322.4 210.05,-3322.4 235.05,-3322.4 260.05,-3322.4 285.05,-3322.4 310.05,-3322.4 335.05,-3322.4 360.05,-3322.4 -439.95,-3297.4 -414.95,-3297.4 -389.95,-3297.4 -364.95,-3297.4 -339.95,-3297.4 -314.95,-3297.4 -289.95,-3297.4 -264.95,-3297.4 -239.95,-3297.4 -214.95,-3297.4 -189.95,-3297.4 -164.95,-3297.4 -139.95,-3297.4 -114.95,-3297.4 -89.95,-3297.4 -64.95,-3297.4 -39.95,-3297.4 -14.95,-3297.4 10.05,-3297.4 35.05,-3297.4 60.05,-3297.4 85.05,-3297.4 110.05,-3297.4 135.05,-3297.4 160.05,-3297.4 185.05,-3297.4 210.05,-3297.4 235.05,-3297.4 260.05,-3297.4 285.05,-3297.4 310.05,-3297.4 335.05,-3297.4 360.05,-3297.4 -439.95,-3272.4 -414.95,-3272.4 -389.95,-3272.4 -364.95,-3272.4 -339.95,-3272.4 -314.95,-3272.4 -289.95,-3272.4 -264.95,-3272.4 -239.95,-3272.4 -214.95,-3272.4 -189.95,-3272.4 -164.95,-3272.4 -139.95,-3272.4 -114.95,-3272.4 -89.95,-3272.4 -64.95,-3272.4 -39.95,-3272.4 -14.95,-3272.4 10.05,-3272.4 35.05,-3272.4 60.05,-3272.4 85.05,-3272.4 110.05,-3272.4 135.05,-3272.4 160.05,-3272.4 185.05,-3272.4 210.05,-3272.4 235.05,-3272.4 260.05,-3272.4 285.05,-3272.4 310.05,-3272.4 335.05,-3272.4 360.05,-3272.4 -439.95,-3247.4 -414.95,-3247.4 -389.95,-3247.4 -364.95,-3247.4 -339.95,-3247.4 -314.95,-3247.4 -289.95,-3247.4 -264.95,-3247.4 -239.95,-3247.4 -214.95,-3247.4 -189.95,-3247.4 -164.95,-3247.4 -139.95,-3247.4 -114.95,-3247.4 -89.95,-3247.4 -64.95,-3247.4 -39.95,-3247.4 -14.95,-3247.4 10.05,-3247.4 35.05,-3247.4 60.05,-3247.4 85.05,-3247.4 110.05,-3247.4 135.05,-3247.4 160.05,-3247.4 185.05,-3247.4 210.05,-3247.4 235.05,-3247.4 260.05,-3247.4 285.05,-3247.4 310.05,-3247.4 335.05,-3247.4 360.05,-3247.4 -439.95,-3222.4 -414.95,-3222.4 -389.95,-3222.4 -364.95,-3222.4 -339.95,-3222.4 -314.95,-3222.4 -289.95,-3222.4 -264.95,-3222.4 -239.95,-3222.4 -214.95,-3222.4 -189.95,-3222.4 -164.95,-3222.4 -139.95,-3222.4 -114.95,-3222.4 -89.95,-3222.4 -64.95,-3222.4 -39.95,-3222.4 -14.95,-3222.4 10.05,-3222.4 35.05,-3222.4 60.05,-3222.4 85.05,-3222.4 110.05,-3222.4 135.05,-3222.4 160.05,-3222.4 185.05,-3222.4 210.05,-3222.4 235.05,-3222.4 260.05,-3222.4 285.05,-3222.4 310.05,-3222.4 335.05,-3222.4 360.05,-3222.4 -439.95,-3197.4 -414.95,-3197.4 -389.95,-3197.4 -364.95,-3197.4 -339.95,-3197.4 -314.95,-3197.4 -289.95,-3197.4 -264.95,-3197.4 -239.95,-3197.4 -214.95,-3197.4 -189.95,-3197.4 -164.95,-3197.4 -139.95,-3197.4 -114.95,-3197.4 -89.95,-3197.4 -64.95,-3197.4 -39.95,-3197.4 -14.95,-3197.4 10.05,-3197.4 35.05,-3197.4 60.05,-3197.4 85.05,-3197.4 110.05,-3197.4 135.05,-3197.4 160.05,-3197.4 185.05,-3197.4 210.05,-3197.4 235.05,-3197.4 260.05,-3197.4 285.05,-3197.4 310.05,-3197.4 335.05,-3197.4 360.05,-3197.4 -439.95,-3172.4 -414.95,-3172.4 -389.95,-3172.4 -364.95,-3172.4 -339.95,-3172.4 -314.95,-3172.4 -289.95,-3172.4 -264.95,-3172.4 -239.95,-3172.4 -214.95,-3172.4 -189.95,-3172.4 -164.95,-3172.4 -139.95,-3172.4 -114.95,-3172.4 -89.95,-3172.4 -64.95,-3172.4 -39.95,-3172.4 -14.95,-3172.4 10.05,-3172.4 35.05,-3172.4 60.05,-3172.4 85.05,-3172.4 110.05,-3172.4 135.05,-3172.4 160.05,-3172.4 185.05,-3172.4 210.05,-3172.4 235.05,-3172.4 260.05,-3172.4 285.05,-3172.4 310.05,-3172.4 335.05,-3172.4 360.05,-3172.4 -439.95,-3147.4 -414.95,-3147.4 -389.95,-3147.4 -364.95,-3147.4 -339.95,-3147.4 -314.95,-3147.4 -289.95,-3147.4 -264.95,-3147.4 -239.95,-3147.4 -214.95,-3147.4 -189.95,-3147.4 -164.95,-3147.4 -139.95,-3147.4 -114.95,-3147.4 -89.95,-3147.4 -64.95,-3147.4 -39.95,-3147.4 -14.95,-3147.4 10.05,-3147.4 35.05,-3147.4 60.05,-3147.4 85.05,-3147.4 110.05,-3147.4 135.05,-3147.4 160.05,-3147.4 185.05,-3147.4 210.05,-3147.4 235.05,-3147.4 260.05,-3147.4 285.05,-3147.4 310.05,-3147.4 335.05,-3147.4 360.05,-3147.4 -414.95,-3122.4 -389.95,-3122.4 -364.95,-3122.4 -339.95,-3122.4 -314.95,-3122.4 -289.95,-3122.4 -264.95,-3122.4 -239.95,-3122.4 -214.95,-3122.4 -189.95,-3122.4 -164.95,-3122.4 -139.95,-3122.4 -114.95,-3122.4 -89.95,-3122.4 -64.95,-3122.4 -39.95,-3122.4 -14.95,-3122.4 10.05,-3122.4 35.05,-3122.4 60.05,-3122.4 85.05,-3122.4 110.05,-3122.4 135.05,-3122.4 160.05,-3122.4 185.05,-3122.4 210.05,-3122.4 235.05,-3122.4 260.05,-3122.4 285.05,-3122.4 310.05,-3122.4 335.05,-3122.4
-VIN: C1.3 C1.4 C2.3 C2.4 C3.3 C3.4 C4.3 C4.4 C5.1 C6.1 C7.1 C8.1 C9.1 C10.1 C11.1 C12.1 C13.1 C14.1 C15.1 C16.1 C17.1 C18.1 C19.1 C20.1 C21.1 C22.1 C23.1 C24.1 C25.1 C26.1 C27.1 C28.1 C29.1 C30.1 C31.1 C32.1 C33.1 C34.1 C35.3 C35.4 JT1.1 JT1.2 JT1.3 JT1.4 JT1.5 JT1.6 JT2.1 JT2.2 JT2.3 JT2.4 JT2.5 JT2.6 R16.1 R17.1 R18.1 RT1.8 RT1.9 RT1.10 RT1.11 RT1.12 RT1.13 RT1.14
  other v1: -1990,568.94 -1940,568.94 -1890,568.94 -1840,568.94 -1790,568.94 -1740,568.94 -1690,568.94 -1640,568.94 -1590,568.94 -1540,568.94 -1490,568.94 -1440,568.94 -1390,568.94 -1340,568.94 -1290,568.94 -1240,568.94 -1190,568.94 -1140,568.94 -1090,568.94 -1040,568.94 -990,568.94 -940,568.94 -890,568.94 -840,568.94 -790,568.94 -740,568.94 -690,568.94 -640,568.94 -590,568.94 -540,568.94 -490,568.94 -440,568.94 -390,568.94 -340,568.94 -290,568.94 -240,568.94 -190,568.94 -140,568.94 -90,568.94 -40,568.94 10,568.94 60,568.94 110,568.94 160,568.94 210,568.94 260,568.94 310,568.94 360,568.94 410,568.94 460,568.94 510,568.94 560,568.94 610,568.94 660,568.94 710,568.94 760,568.94 810,568.94 860,568.94 910,568.94 960,568.94 1010,568.94 1060,568.94 1110,568.94 1160,568.94 1210,568.94 1260,568.94 1310,568.94 1360,568.94 1410,568.94 1460,568.94 1510,568.94 1560,568.94 1610,568.94 1660,568.94 1710,568.94 1760,568.94 1810,568.94 1860,568.94 1910,568.94 -1990,618.94 -1940,618.94 -1890,618.94 -1840,618.94 -1790,618.94 -1740,618.94 -1690,618.94 -1640,618.94 -1590,618.94 -1540,618.94 -1490,618.94 -1440,618.94 -1390,618.94 -1340,618.94 -1290,618.94 -1240,618.94 -1190,618.94 -1140,618.94 -1090,618.94 -1040,618.94 -990,618.94 -940,618.94 -890,618.94 -840,618.94 -790,618.94 -740,618.94 -690,618.94 -640,618.94 -590,618.94 -540,618.94 -490,618.94 -440,618.94 -390,618.94 -340,618.94 -290,618.94 -240,618.94 -190,618.94 -140,618.94 -90,618.94 -40,618.94 10,618.94 60,618.94 110,618.94 160,618.94 210,618.94 260,618.94 310,618.94 360,618.94 410,618.94 460,618.94 510,618.94 560,618.94 610,618.94 660,618.94 710,618.94 760,618.94 810,618.94 860,618.94 910,618.94 960,618.94 1010,618.94 1060,618.94 1110,618.94 1160,618.94 1210,618.94 1260,618.94 1310,618.94 1360,618.94 1410,618.94 1460,618.94 1510,618.94 1560,618.94 1610,618.94 1660,618.94 1710,618.94 1760,618.94 1810,618.94 1860,618.94 1910,618.94 -1990,668.94 -1940,668.94 -1890,668.94 -1840,668.94 -1790,668.94 -1740,668.94 -1690,668.94 -1640,668.94 -1440,668.94 -1390,668.94 -1340,668.94 -1290,668.94 -1240,668.94 -1190,668.94 -1140,668.94 -940,668.94 -890,668.94 -840,668.94 -790,668.94 -740,668.94 -690,668.94 -640,668.94 -440,668.94 -390,668.94 -340,668.94 -290,668.94 -240,668.94 -190,668.94 -140,668.94 60,668.94 110,668.94 160,668.94 210,668.94 260,668.94 310,668.94 360,668.94 560,668.94 610,668.94 660,668.94 710,668.94 760,668.94 810,668.94 860,668.94 1060,668.94 1110,668.94 1160,668.94 1210,668.94 1260,668.94 1310,668.94 1360,668.94 1560,668.94 1610,668.94 1660,668.94 1710,668.94 1760,668.94 1810,668.94 1860,668.94 1910,668.94 -1990,718.94 -1940,718.94 -1890,718.94 -1840,718.94 -1790,718.94 -1740,718.94 -1690,718.94 -1640,718.94 -1440,718.94 -1390,718.94 -1340,718.94 -1290,718.94 -1240,718.94 -1190,718.94 -1140,718.94 -940,718.94 -890,718.94 -840,718.94 -790,718.94 -740,718.94 -690,718.94 -640,718.94 -440,718.94 -390,718.94 -340,718.94 -290,718.94 -240,718.94 -190,718.94 -140,718.94 60,718.94 110,718.94 160,718.94 210,718.94 260,718.94 310,718.94 360,718.94 560,718.94 610,718.94 660,718.94 710,718.94 760,718.94 810,718.94 860,718.94 1060,718.94 1110,718.94 1160,718.94 1210,718.94 1260,718.94 1310,718.94 1360,718.94 1560,718.94 1610,718.94 1660,718.94 1710,718.94 1760,718.94 1810,718.94 1860,718.94 1910,718.94 -1990,768.94 -1940,768.94 -1890,768.94 -1840,768.94 -1790,768.94 -1740,768.94 -1690,768.94 -1640,768.94 -1440,768.94 -1390,768.94 -1340,768.94 -1290,768.94 -1240,768.94 -1190,768.94 -1140,768.94 -940,768.94 -890,768.94 -840,768.94 -790,768.94 -740,768.94 -690,768.94 -640,768.94 -440,768.94 -390,768.94 -340,768.94 -290,768.94 -240,768.94 -190,768.94 -140,768.94 60,768.94 110,768.94 160,768.94 210,768.94 260,768.94 310,768.94 360,768.94 560,768.94 610,768.94 660,768.94 710,768.94 760,768.94 810,768.94 860,768.94 1060,768.94 1110,768.94 1160,768.94 1210,768.94 1260,768.94 1310,768.94 1360,768.94 1560,768.94 1610,768.94 1660,768.94 1710,768.94 1760,768.94 1810,768.94 1860,768.94 1910,768.94 -1990,818.94 -1940,818.94 -1890,818.94 -1840,818.94 -1790,818.94 -1740,818.94 -1690,818.94 -1640,818.94 -1440,818.94 -1390,818.94 -1340,818.94 -1290,818.94 -1240,818.94 -1190,818.94 -1140,818.94 -940,818.94 -890,818.94 -840,818.94 -790,818.94 -740,818.94 -690,818.94 -640,818.94 -440,818.94 -390,818.94 -340,818.94 -290,818.94 -240,818.94 -190,818.94 -140,818.94 60,818.94 110,818.94 160,818.94 210,818.94 260,818.94 310,818.94 360,818.94 560,818.94 610,818.94 660,818.94 710,818.94 760,818.94 810,818.94 860,818.94 1060,818.94 1110,818.94 1160,818.94 1210,818.94 1260,818.94 1310,818.94 1360,818.94 1560,818.94 1610,818.94 1660,818.94 1710,818.94 1760,818.94 1810,818.94 1860,818.94 1910,818.94 -1990,868.94 -1940,868.94 -1890,868.94 -1840,868.94 -1790,868.94 -1740,868.94 -1690,868.94 -1640,868.94 -1440,868.94 -1390,868.94 -1340,868.94 -1290,868.94 -1240,868.94 -1190,868.94 -1140,868.94 -940,868.94 -890,868.94 -840,868.94 -790,868.94 -740,868.94 -690,868.94 -640,868.94 -440,868.94 -390,868.94 -340,868.94 -290,868.94 -240,868.94 -190,868.94 -140,868.94 60,868.94 110,868.94 160,868.94 210,868.94 260,868.94 310,868.94 360,868.94 560,868.94 610,868.94 660,868.94 710,868.94 760,868.94 810,868.94 860,868.94 1060,868.94 1110,868.94 1160,868.94 1210,868.94 1260,868.94 1310,868.94 1360,868.94 1560,868.94 1610,868.94 1660,868.94 1710,868.94 1760,868.94 1810,868.94 1860,868.94 1910,868.94 -1990,918.94 -1940,918.94 -1890,918.94 -1840,918.94 -1790,918.94 -1740,918.94 -1690,918.94 -1640,918.94 -1590,918.94 -1540,918.94 -1490,918.94 -1440,918.94 -1390,918.94 -1340,918.94 -1290,918.94 -1240,918.94 -1190,918.94 -1140,918.94 -1090,918.94 -1040,918.94 -990,918.94 -940,918.94 -890,918.94 -840,918.94 -790,918.94 -740,918.94 -690,918.94 -640,918.94 -590,918.94 -540,918.94 -490,918.94 -440,918.94 -390,918.94 -340,918.94 -290,918.94 -240,918.94 -190,918.94 -140,918.94 -90,918.94 -40,918.94 10,918.94 60,918.94 110,918.94 160,918.94 210,918.94 260,918.94 310,918.94 360,918.94 410,918.94 460,918.94 510,918.94 560,918.94 610,918.94 660,918.94 710,918.94 760,918.94 810,918.94 860,918.94 910,918.94 960,918.94 1010,918.94 1060,918.94 1110,918.94 1160,918.94 1210,918.94 1260,918.94 1310,918.94 1360,918.94 1410,918.94 1460,918.94 1510,918.94 1560,918.94 1610,918.94 1660,918.94 1710,918.94 1760,918.94 1810,918.94 1860,918.94 1910,918.94 -1990,968.94 -1940,968.94 -1890,968.94 -1840,968.94 -1790,968.94 -1740,968.94 -1690,968.94 -1640,968.94 -1590,968.94 -1540,968.94 -1490,968.94 -1440,968.94 -1390,968.94 -1340,968.94 -1290,968.94 -1240,968.94 -1190,968.94 -1140,968.94 -1090,968.94 -1040,968.94 -990,968.94 -940,968.94 -890,968.94 -840,968.94 -790,968.94 -740,968.94 -690,968.94 -640,968.94 -590,968.94 -540,968.94 -490,968.94 -440,968.94 -390,968.94 -340,968.94 -290,968.94 -240,968.94 -190,968.94 -140,968.94 -90,968.94 -40,968.94 10,968.94 60,968.94 110,968.94 160,968.94 210,968.94 260,968.94 310,968.94 360,968.94 410,968.94 460,968.94 510,968.94 560,968.94 610,968.94 660,968.94 710,968.94 760,968.94 810,968.94 860,968.94 910,968.94 960,968.94 1010,968.94 1060,968.94 1110,968.94 1160,968.94 1210,968.94 1260,968.94 1310,968.94 1360,968.94 1410,968.94 1460,968.94 1510,968.94 1560,968.94 1610,968.94 1660,968.94 1710,968.94 1760,968.94 1810,968.94 1860,968.94 1910,968.94 -1990,1018.94 -1940,1018.94 -1890,1018.94 -1840,1018.94 -1790,1018.94 -1740,1018.94 -1690,1018.94 -1640,1018.94 -1590,1018.94 -1540,1018.94 -1490,1018.94 -1440,1018.94 -1390,1018.94 -1340,1018.94 -1290,1018.94 -1240,1018.94 -1190,1018.94 -1140,1018.94 -1090,1018.94 -1040,1018.94 -990,1018.94 -940,1018.94 -890,1018.94 -840,1018.94 -790,1018.94 -740,1018.94 -690,1018.94 -640,1018.94 -590,1018.94 -540,1018.94 -490,1018.94 -440,1018.94 -390,1018.94 -340,1018.94 -290,1018.94 -240,1018.94 -190,1018.94 -140,1018.94 -90,1018.94 -40,1018.94 10,1018.94 60,1018.94 110,1018.94 160,1018.94 210,1018.94 260,1018.94 310,1018.94 360,1018.94 410,1018.94 460,1018.94 510,1018.94 560,1018.94 610,1018.94 660,1018.94 710,1018.94 760,1018.94 810,1018.94 860,1018.94 910,1018.94 960,1018.94 1010,1018.94 1060,1018.94 1110,1018.94 1160,1018.94 1210,1018.94 1260,1018.94 1310,1018.94 1360,1018.94 1410,1018.94 1460,1018.94 1510,1018.94 1560,1018.94 1610,1018.94 1660,1018.94 1710,1018.94 1760,1018.94 1810,1018.94 1860,1018.94 1910,1018.94
MIDPOINT: JT3.1 JT3.2 JT3.3 JT3.4 JT3.5 JT3.6 TP2.1 U1.1 | length 1288.2
  TOP w25: U1.1@-39.95,-1320.04 TP2.1@840,-1320.04
  LAYER2 w25: U1.1@-39.95,-1320.04 -19.91,-1300 260.05,-1300 U1.1@360.05,-1300
  other v1: -414.95,-1722.4 -389.95,-1722.4 -364.95,-1722.4 -339.95,-1722.4 -314.95,-1722.4 -289.95,-1722.4 -264.95,-1722.4 -239.95,-1722.4 -214.95,-1722.4 -189.95,-1722.4 -164.95,-1722.4 -139.95,-1722.4 -114.95,-1722.4 -89.95,-1722.4 -64.95,-1722.4 -39.95,-1722.4 -14.95,-1722.4 10.05,-1722.4 35.05,-1722.4 60.05,-1722.4 85.05,-1722.4 110.05,-1722.4 135.05,-1722.4 160.05,-1722.4 185.05,-1722.4 210.05,-1722.4 235.05,-1722.4 260.05,-1722.4 285.05,-1722.4 310.05,-1722.4 335.05,-1722.4 -439.95,-1697.4 -414.95,-1697.4 -389.95,-1697.4 -364.95,-1697.4 -339.95,-1697.4 -314.95,-1697.4 -289.95,-1697.4 -264.95,-1697.4 -239.95,-1697.4 -214.95,-1697.4 -189.95,-1697.4 -164.95,-1697.4 -139.95,-1697.4 -114.95,-1697.4 -89.95,-1697.4 -64.95,-1697.4 -39.95,-1697.4 -14.95,-1697.4 10.05,-1697.4 35.05,-1697.4 60.05,-1697.4 85.05,-1697.4 110.05,-1697.4 135.05,-1697.4 160.05,-1697.4 185.05,-1697.4 210.05,-1697.4 235.05,-1697.4 260.05,-1697.4 285.05,-1697.4 310.05,-1697.4 335.05,-1697.4 360.05,-1697.4 -439.95,-1672.4 -414.95,-1672.4 -389.95,-1672.4 -364.95,-1672.4 -339.95,-1672.4 -314.95,-1672.4 -289.95,-1672.4 -264.95,-1672.4 -239.95,-1672.4 -214.95,-1672.4 -189.95,-1672.4 -164.95,-1672.4 -139.95,-1672.4 -114.95,-1672.4 -89.95,-1672.4 -64.95,-1672.4 -39.95,-1672.4 -14.95,-1672.4 10.05,-1672.4 35.05,-1672.4 60.05,-1672.4 85.05,-1672.4 110.05,-1672.4 135.05,-1672.4 160.05,-1672.4 185.05,-1672.4 210.05,-1672.4 235.05,-1672.4 260.05,-1672.4 285.05,-1672.4 310.05,-1672.4 335.05,-1672.4 360.05,-1672.4 -439.95,-1647.4 -414.95,-1647.4 -389.95,-1647.4 -364.95,-1647.4 -339.95,-1647.4 -314.95,-1647.4 -289.95,-1647.4 -264.95,-1647.4 -239.95,-1647.4 -214.95,-1647.4 -189.95,-1647.4 -164.95,-1647.4 -139.95,-1647.4 -114.95,-1647.4 -89.95,-1647.4 -64.95,-1647.4 -39.95,-1647.4 -14.95,-1647.4 10.05,-1647.4 35.05,-1647.4 60.05,-1647.4 85.05,-1647.4 110.05,-1647.4 135.05,-1647.4 160.05,-1647.4 185.05,-1647.4 210.05,-1647.4 235.05,-1647.4 260.05,-1647.4 285.05,-1647.4 310.05,-1647.4 335.05,-1647.4 360.05,-1647.4 -439.95,-1622.4 -414.95,-1622.4 -389.95,-1622.4 -364.95,-1622.4 -339.95,-1622.4 -314.95,-1622.4 -289.95,-1622.4 -264.95,-1622.4 -239.95,-1622.4 -214.95,-1622.4 -189.95,-1622.4 -164.95,-1622.4 -139.95,-1622.4 -114.95,-1622.4 -89.95,-1622.4 -64.95,-1622.4 -39.95,-1622.4 -14.95,-1622.4 10.05,-1622.4 35.05,-1622.4 60.05,-1622.4 85.05,-1622.4 110.05,-1622.4 135.05,-1622.4 160.05,-1622.4 185.05,-1622.4 210.05,-1622.4 235.05,-1622.4 260.05,-1622.4 285.05,-1622.4 310.05,-1622.4 335.05,-1622.4 360.05,-1622.4 -439.95,-1597.4 -414.95,-1597.4 -389.95,-1597.4 -364.95,-1597.4 -339.95,-1597.4 -314.95,-1597.4 -289.95,-1597.4 -264.95,-1597.4 -239.95,-1597.4 -214.95,-1597.4 -189.95,-1597.4 -164.95,-1597.4 -139.95,-1597.4 -114.95,-1597.4 -89.95,-1597.4 -64.95,-1597.4 -39.95,-1597.4 -14.95,-1597.4 10.05,-1597.4 35.05,-1597.4 60.05,-1597.4 85.05,-1597.4 110.05,-1597.4 135.05,-1597.4 160.05,-1597.4 185.05,-1597.4 210.05,-1597.4 235.05,-1597.4 260.05,-1597.4 285.05,-1597.4 310.05,-1597.4 335.05,-1597.4 360.05,-1597.4 -439.95,-1572.4 -414.95,-1572.4 -389.95,-1572.4 -364.95,-1572.4 -339.95,-1572.4 -314.95,-1572.4 -289.95,-1572.4 -264.95,-1572.4 -239.95,-1572.4 -214.95,-1572.4 -189.95,-1572.4 -164.95,-1572.4 -139.95,-1572.4 -114.95,-1572.4 -89.95,-1572.4 -64.95,-1572.4 -39.95,-1572.4 -14.95,-1572.4 10.05,-1572.4 35.05,-1572.4 60.05,-1572.4 85.05,-1572.4 110.05,-1572.4 135.05,-1572.4 160.05,-1572.4 185.05,-1572.4 210.05,-1572.4 235.05,-1572.4 260.05,-1572.4 285.05,-1572.4 310.05,-1572.4 335.05,-1572.4 360.05,-1572.4 -439.95,-1547.4 -414.95,-1547.4 -389.95,-1547.4 -364.95,-1547.4 -339.95,-1547.4 -314.95,-1547.4 -289.95,-1547.4 -264.95,-1547.4 -239.95,-1547.4 -214.95,-1547.4 -189.95,-1547.4 -164.95,-1547.4 -139.95,-1547.4 -114.95,-1547.4 -89.95,-1547.4 -64.95,-1547.4 -39.95,-1547.4 -14.95,-1547.4 10.05,-1547.4 35.05,-1547.4 60.05,-1547.4 85.05,-1547.4 110.05,-1547.4 135.05,-1547.4 160.05,-1547.4 185.05,-1547.4 210.05,-1547.4 235.05,-1547.4 260.05,-1547.4 285.05,-1547.4 310.05,-1547.4 335.05,-1547.4 360.05,-1547.4 -439.95,-1522.4 -414.95,-1522.4 -389.95,-1522.4 -364.95,-1522.4 -339.95,-1522.4 -314.95,-1522.4 -289.95,-1522.4 -264.95,-1522.4 -239.95,-1522.4 -214.95,-1522.4 -189.95,-1522.4 -164.95,-1522.4 -139.95,-1522.4 -114.95,-1522.4 -89.95,-1522.4 -64.95,-1522.4 -39.95,-1522.4 -14.95,-1522.4 10.05,-1522.4 35.05,-1522.4 60.05,-1522.4 85.05,-1522.4 110.05,-1522.4 135.05,-1522.4 160.05,-1522.4 185.05,-1522.4 210.05,-1522.4 235.05,-1522.4 260.05,-1522.4 285.05,-1522.4 310.05,-1522.4 335.05,-1522.4 360.05,-1522.4 -439.95,-1497.4 -414.95,-1497.4 -389.95,-1497.4 -364.95,-1497.4 -339.95,-1497.4 -314.95,-1497.4 -289.95,-1497.4 -264.95,-1497.4 -239.95,-1497.4 -214.95,-1497.4 -189.95,-1497.4 -164.95,-1497.4 -139.95,-1497.4 -114.95,-1497.4 -89.95,-1497.4 -64.95,-1497.4 -39.95,-1497.4 -14.95,-1497.4 10.05,-1497.4 35.05,-1497.4 60.05,-1497.4 85.05,-1497.4 110.05,-1497.4 135.05,-1497.4 160.05,-1497.4 185.05,-1497.4 210.05,-1497.4 235.05,-1497.4 260.05,-1497.4 285.05,-1497.4 310.05,-1497.4 335.05,-1497.4 360.05,-1497.4 -439.95,-1472.4 -414.95,-1472.4 -389.95,-1472.4 -364.95,-1472.4 -339.95,-1472.4 -314.95,-1472.4 -289.95,-1472.4 -264.95,-1472.4 -239.95,-1472.4 -214.95,-1472.4 -189.95,-1472.4 -164.95,-1472.4 -139.95,-1472.4 -114.95,-1472.4 -89.95,-1472.4 -64.95,-1472.4 -39.95,-1472.4 -14.95,-1472.4 10.05,-1472.4 35.05,-1472.4 60.05,-1472.4 85.05,-1472.4 110.05,-1472.4 135.05,-1472.4 160.05,-1472.4 185.05,-1472.4 210.05,-1472.4 235.05,-1472.4 260.05,-1472.4 285.05,-1472.4 310.05,-1472.4 335.05,-1472.4 360.05,-1472.4 -439.95,-1447.4 -414.95,-1447.4 -389.95,-1447.4 -364.95,-1447.4 -339.95,-1447.4 -314.95,-1447.4 -289.95,-1447.4 -264.95,-1447.4 -239.95,-1447.4 -214.95,-1447.4 -189.95,-1447.4 -164.95,-1447.4 -139.95,-1447.4 60.05,-1447.4 85.05,-1447.4 110.05,-1447.4 135.05,-1447.4 160.05,-1447.4 185.05,-1447.4 210.05,-1447.4 235.05,-1447.4 260.05,-1447.4 285.05,-1447.4 310.05,-1447.4 335.05,-1447.4 360.05,-1447.4 -439.95,-1422.4 -414.95,-1422.4 -389.95,-1422.4 -364.95,-1422.4 -339.95,-1422.4 -314.95,-1422.4 -289.95,-1422.4 -264.95,-1422.4 -239.95,-1422.4 -214.95,-1422.4 -189.95,-1422.4 -164.95,-1422.4 85.05,-1422.4 110.05,-1422.4 135.05,-1422.4 160.05,-1422.4 185.05,-1422.4 210.05,-1422.4 235.05,-1422.4 260.05,-1422.4 285.05,-1422.4 310.05,-1422.4 335.05,-1422.4 360.05,-1422.4 -439.95,-1397.4 -414.95,-1397.4 -389.95,-1397.4 -364.95,-1397.4 -339.95,-1397.4 -314.95,-1397.4 -289.95,-1397.4 -264.95,-1397.4 -239.95,-1397.4 -214.95,-1397.4 -189.95,-1397.4 110.05,-1397.4 135.05,-1397.4 160.05,-1397.4 185.05,-1397.4 210.05,-1397.4 235.05,-1397.4 260.05,-1397.4 285.05,-1397.4 310.05,-1397.4 335.05,-1397.4 360.05,-1397.4 -439.95,-1372.4 -414.95,-1372.4 -389.95,-1372.4 -364.95,-1372.4 -339.95,-1372.4 -314.95,-1372.4 -289.95,-1372.4 -264.95,-1372.4 -239.95,-1372.4 -214.95,-1372.4 -189.95,-1372.4 110.05,-1372.4 135.05,-1372.4 160.05,-1372.4 185.05,-1372.4 210.05,-1372.4 235.05,-1372.4 260.05,-1372.4 285.05,-1372.4 310.05,-1372.4 335.05,-1372.4 360.05,-1372.4 -439.95,-1347.4 -414.95,-1347.4 -389.95,-1347.4 -364.95,-1347.4 -339.95,-1347.4 -314.95,-1347.4 -289.95,-1347.4 -264.95,-1347.4 -239.95,-1347.4 -214.95,-1347.4 -189.95,-1347.4 110.05,-1347.4 135.05,-1347.4 160.05,-1347.4 185.05,-1347.4 210.05,-1347.4 235.05,-1347.4 260.05,-1347.4 285.05,-1347.4 310.05,-1347.4 335.05,-1347.4 360.05,-1347.4 -439.95,-1322.4 -414.95,-1322.4 -389.95,-1322.4 -364.95,-1322.4 -339.95,-1322.4 -314.95,-1322.4 -289.95,-1322.4 -264.95,-1322.4 -239.95,-1322.4 -214.95,-1322.4 -189.95,-1322.4 110.05,-1322.4 135.05,-1322.4 160.05,-1322.4 185.05,-1322.4 210.05,-1322.4 235.05,-1322.4 260.05,-1322.4 285.05,-1322.4 310.05,-1322.4 335.05,-1322.4 360.05,-1322.4 -439.95,-1297.4 -414.95,-1297.4 -389.95,-1297.4 -364.95,-1297.4 -339.95,-1297.4 -314.95,-1297.4 -289.95,-1297.4 -264.95,-1297.4 -239.95,-1297.4 -214.95,-1297.4 -189.95,-1297.4 110.05,-1297.4 135.05,-1297.4 160.05,-1297.4 185.05,-1297.4 210.05,-1297.4 235.05,-1297.4 260.05,-1297.4 285.05,-1297.4 310.05,-1297.4 335.05,-1297.4 360.05,-1297.4 -439.95,-1272.4 -414.95,-1272.4 -389.95,-1272.4 -364.95,-1272.4 -339.95,-1272.4 -314.95,-1272.4 -289.95,-1272.4 -264.95,-1272.4 -239.95,-1272.4 -214.95,-1272.4 -189.95,-1272.4 110.05,-1272.4 135.05,-1272.4 160.05,-1272.4 185.05,-1272.4 210.05,-1272.4 235.05,-1272.4 260.05,-1272.4 285.05,-1272.4 310.05,-1272.4 335.05,-1272.4 360.05,-1272.4 -439.95,-1247.4 -414.95,-1247.4 -389.95,-1247.4 -364.95,-1247.4 -339.95,-1247.4 -314.95,-1247.4 -289.95,-1247.4 -264.95,-1247.4 -239.95,-1247.4 -214.95,-1247.4 -189.95,-1247.4 110.05,-1247.4 135.05,-1247.4 160.05,-1247.4 185.05,-1247.4 210.05,-1247.4 235.05,-1247.4 260.05,-1247.4 285.05,-1247.4 310.05,-1247.4 335.05,-1247.4 360.05,-1247.4 -439.95,-1222.4 -414.95,-1222.4 -389.95,-1222.4 -364.95,-1222.4 -339.95,-1222.4 -314.95,-1222.4 -289.95,-1222.4 -264.95,-1222.4 -239.95,-1222.4 -214.95,-1222.4 -189.95,-1222.4 -164.95,-1222.4 85.05,-1222.4 110.05,-1222.4 135.05,-1222.4 160.05,-1222.4 185.05,-1222.4 210.05,-1222.4 235.05,-1222.4 260.05,-1222.4 285.05,-1222.4 310.05,-1222.4 335.05,-1222.4 360.05,-1222.4 -439.95,-1197.4 -414.95,-1197.4 -389.95,-1197.4 -364.95,-1197.4 -339.95,-1197.4 -314.95,-1197.4 -289.95,-1197.4 -264.95,-1197.4 -239.95,-1197.4 -214.95,-1197.4 -189.95,-1197.4 -164.95,-1197.4 -139.95,-1197.4 60.05,-1197.4 85.05,-1197.4 110.05,-1197.4 135.05,-1197.4 160.05,-1197.4 185.05,-1197.4 210.05,-1197.4 235.05,-1197.4 260.05,-1197.4 285.05,-1197.4 310.05,-1197.4 335.05,-1197.4 360.05,-1197.4 -439.95,-1172.4 -414.95,-1172.4 -389.95,-1172.4 -364.95,-1172.4 -339.95,-1172.4 -314.95,-1172.4 -289.95,-1172.4 -264.95,-1172.4 -239.95,-1172.4 -214.95,-1172.4 -189.95,-1172.4 -164.95,-1172.4 -139.95,-1172.4 -114.95,-1172.4 -89.95,-1172.4 -64.95,-1172.4 -39.95,-1172.4 -14.95,-1172.4 10.05,-1172.4 35.05,-1172.4 60.05,-1172.4 85.05,-1172.4 110.05,-1172.4 135.05,-1172.4 160.05,-1172.4 185.05,-1172.4 210.05,-1172.4 235.05,-1172.4 260.05,-1172.4 285.05,-1172.4 310.05,-1172.4 335.05,-1172.4 360.05,-1172.4 -439.95,-1147.4 -414.95,-1147.4 -389.95,-1147.4 -364.95,-1147.4 -339.95,-1147.4 -314.95,-1147.4 -289.95,-1147.4 -264.95,-1147.4 -239.95,-1147.4 -214.95,-1147.4 -189.95,-1147.4 -164.95,-1147.4 -139.95,-1147.4 -114.95,-1147.4 -89.95,-1147.4 -64.95,-1147.4 -39.95,-1147.4 -14.95,-1147.4 10.05,-1147.4 35.05,-1147.4 60.05,-1147.4 85.05,-1147.4 110.05,-1147.4 135.05,-1147.4 160.05,-1147.4 185.05,-1147.4 210.05,-1147.4 235.05,-1147.4 260.05,-1147.4 285.05,-1147.4 310.05,-1147.4 335.05,-1147.4 360.05,-1147.4 -439.95,-1122.4 -414.95,-1122.4 -389.95,-1122.4 -364.95,-1122.4 -339.95,-1122.4 -314.95,-1122.4 -289.95,-1122.4 -264.95,-1122.4 -239.95,-1122.4 -214.95,-1122.4 -189.95,-1122.4 -164.95,-1122.4 -139.95,-1122.4 -114.95,-1122.4 -89.95,-1122.4 -64.95,-1122.4 -39.95,-1122.4 -14.95,-1122.4 10.05,-1122.4 35.05,-1122.4 60.05,-1122.4 85.05,-1122.4 110.05,-1122.4 135.05,-1122.4 160.05,-1122.4 185.05,-1122.4 210.05,-1122.4 235.05,-1122.4 260.05,-1122.4 285.05,-1122.4 310.05,-1122.4 335.05,-1122.4 360.05,-1122.4 -439.95,-1097.4 -414.95,-1097.4 -389.95,-1097.4 -364.95,-1097.4 -339.95,-1097.4 -314.95,-1097.4 -289.95,-1097.4 -264.95,-1097.4 -239.95,-1097.4 -214.95,-1097.4 -189.95,-1097.4 -164.95,-1097.4 -139.95,-1097.4 -114.95,-1097.4 -89.95,-1097.4 -64.95,-1097.4 -39.95,-1097.4 -14.95,-1097.4 10.05,-1097.4 35.05,-1097.4 60.05,-1097.4 85.05,-1097.4 110.05,-1097.4 135.05,-1097.4 160.05,-1097.4 185.05,-1097.4 210.05,-1097.4 235.05,-1097.4 260.05,-1097.4 285.05,-1097.4 310.05,-1097.4 335.05,-1097.4 360.05,-1097.4 -439.95,-1072.4 -414.95,-1072.4 -389.95,-1072.4 -364.95,-1072.4 -339.95,-1072.4 -314.95,-1072.4 -289.95,-1072.4 -264.95,-1072.4 -239.95,-1072.4 -214.95,-1072.4 -189.95,-1072.4 -164.95,-1072.4 -139.95,-1072.4 -114.95,-1072.4 -89.95,-1072.4 -64.95,-1072.4 -39.95,-1072.4 -14.95,-1072.4 10.05,-1072.4 35.05,-1072.4 60.05,-1072.4 85.05,-1072.4 110.05,-1072.4 135.05,-1072.4 160.05,-1072.4 185.05,-1072.4 210.05,-1072.4 235.05,-1072.4 260.05,-1072.4 285.05,-1072.4 310.05,-1072.4 335.05,-1072.4 360.05,-1072.4 -439.95,-1047.4 -414.95,-1047.4 -389.95,-1047.4 -364.95,-1047.4 -339.95,-1047.4 -314.95,-1047.4 -289.95,-1047.4 -264.95,-1047.4 -239.95,-1047.4 -214.95,-1047.4 -189.95,-1047.4 -164.95,-1047.4 -139.95,-1047.4 -114.95,-1047.4 -89.95,-1047.4 -64.95,-1047.4 -39.95,-1047.4 -14.95,-1047.4 10.05,-1047.4 35.05,-1047.4 60.05,-1047.4 85.05,-1047.4 110.05,-1047.4 135.05,-1047.4 160.05,-1047.4 185.05,-1047.4 210.05,-1047.4 235.05,-1047.4 260.05,-1047.4 285.05,-1047.4 310.05,-1047.4 335.05,-1047.4 360.05,-1047.4 -439.95,-1022.4 -414.95,-1022.4 -389.95,-1022.4 -364.95,-1022.4 -339.95,-1022.4 -314.95,-1022.4 -289.95,-1022.4 -264.95,-1022.4 -239.95,-1022.4 -214.95,-1022.4 -189.95,-1022.4 -164.95,-1022.4 -139.95,-1022.4 -114.95,-1022.4 -89.95,-1022.4 -64.95,-1022.4 -39.95,-1022.4 -14.95,-1022.4 10.05,-1022.4 35.05,-1022.4 60.05,-1022.4 85.05,-1022.4 110.05,-1022.4 135.05,-1022.4 160.05,-1022.4 185.05,-1022.4 210.05,-1022.4 235.05,-1022.4 260.05,-1022.4 285.05,-1022.4 310.05,-1022.4 335.05,-1022.4 360.05,-1022.4 -439.95,-997.4 -414.95,-997.4 -389.95,-997.4 -364.95,-997.4 -339.95,-997.4 -314.95,-997.4 -289.95,-997.4 -264.95,-997.4 -239.95,-997.4 -214.95,-997.4 -189.95,-997.4 -164.95,-997.4 -139.95,-997.4 -114.95,-997.4 -89.95,-997.4 -64.95,-997.4 -39.95,-997.4 -14.95,-997.4 10.05,-997.4 35.05,-997.4 60.05,-997.4 85.05,-997.4 110.05,-997.4 135.05,-997.4 160.05,-997.4 185.05,-997.4 210.05,-997.4 235.05,-997.4 260.05,-997.4 285.05,-997.4 310.05,-997.4 335.05,-997.4 360.05,-997.4 -439.95,-972.4 -414.95,-972.4 -389.95,-972.4 -364.95,-972.4 -339.95,-972.4 -314.95,-972.4 -289.95,-972.4 -264.95,-972.4 -239.95,-972.4 -214.95,-972.4 -189.95,-972.4 -164.95,-972.4 -139.95,-972.4 -114.95,-972.4 -89.95,-972.4 -64.95,-972.4 -39.95,-972.4 -14.95,-972.4 10.05,-972.4 35.05,-972.4 60.05,-972.4 85.05,-972.4 110.05,-972.4 135.05,-972.4 160.05,-972.4 185.05,-972.4 210.05,-972.4 235.05,-972.4 260.05,-972.4 285.05,-972.4 310.05,-972.4 335.05,-972.4 360.05,-972.4 -439.95,-947.4 -414.95,-947.4 -389.95,-947.4 -364.95,-947.4 -339.95,-947.4 -314.95,-947.4 -289.95,-947.4 -264.95,-947.4 -239.95,-947.4 -214.95,-947.4 -189.95,-947.4 -164.95,-947.4 -139.95,-947.4 -114.95,-947.4 -89.95,-947.4 -64.95,-947.4 -39.95,-947.4 -14.95,-947.4 10.05,-947.4 35.05,-947.4 60.05,-947.4 85.05,-947.4 110.05,-947.4 135.05,-947.4 160.05,-947.4 185.05,-947.4 210.05,-947.4 235.05,-947.4 260.05,-947.4 285.05,-947.4 310.05,-947.4 335.05,-947.4 360.05,-947.4 -414.95,-922.4 -389.95,-922.4 -364.95,-922.4 -339.95,-922.4 -314.95,-922.4 -289.95,-922.4 -264.95,-922.4 -239.95,-922.4 -214.95,-922.4 -189.95,-922.4 -164.95,-922.4 -139.95,-922.4 -114.95,-922.4 -89.95,-922.4 -64.95,-922.4 -39.95,-922.4 -14.95,-922.4 10.05,-922.4 35.05,-922.4 60.05,-922.4 85.05,-922.4 110.05,-922.4 135.05,-922.4 160.05,-922.4 185.05,-922.4 210.05,-922.4 235.05,-922.4 260.05,-922.4 285.05,-922.4 310.05,-922.4 335.05,-922.4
